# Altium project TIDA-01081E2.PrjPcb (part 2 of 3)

## Sheet TIDA-01081E2_DigitalIO.SchDoc: Isolated Power & Data Interface
size 431 x 279 mm; Date: Not shown in title block; ApprovedBy: Not shown in title block; CheckedBy: Not shown in title block; Author: Not shown in title block; CompanyName: Not shown in title block; DrawnBy: SG; Engineer: Not shown in title block; Organization: Not shown in title block; Address1: Not shown in title block; Address2: Not shown in title block; Address3: Not shown in title block; Address4: Not shown in title block; DocumentNumber: 7; Revision: Use project parameter SCH_Rev; SheetNumber: 7; SheetTotal: 8; PageSetup: Record=PageOptions¦CenterHorizontal=True¦CenterVertical=True¦PrintScale=0.94¦XCorrection=1.00¦YCorrection=1.00¦PrintKind=0¦BorderSize=5000000¦LeftOffset=0¦BottomOffset=0¦Orientation=2¦PaperLength=4200¦PaperWidth=2970¦Scale=100¦PaperSource=7¦PrintQuality=600¦MediaType=1¦DitherType=10¦PrintScaleMode=1¦PaperKind=A3¦PaperIndex=8
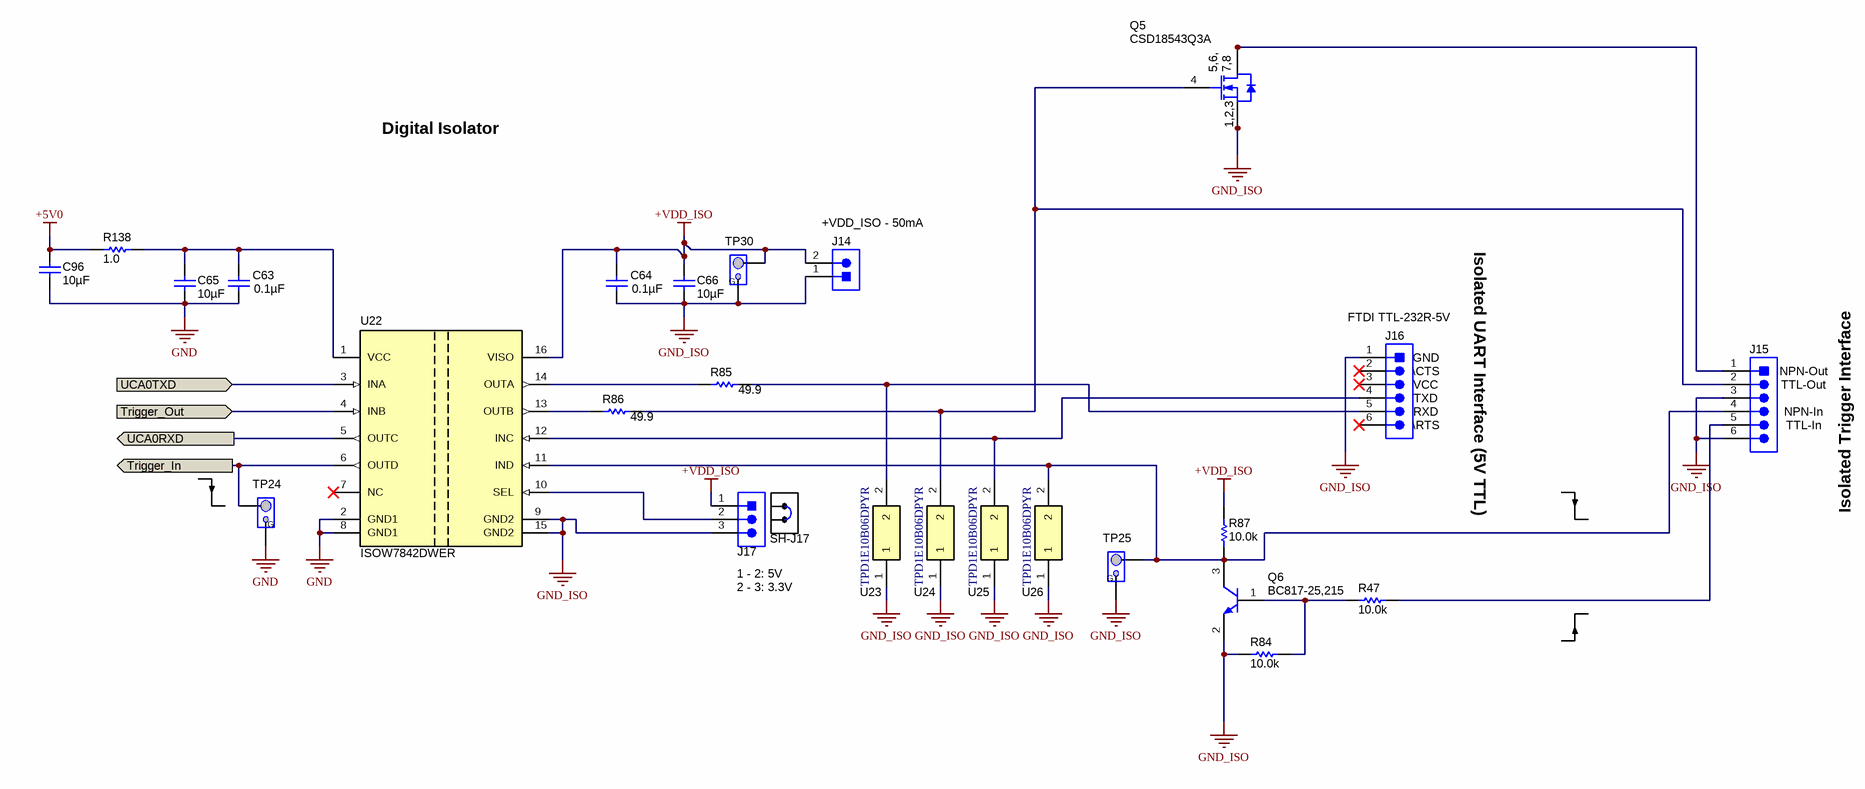
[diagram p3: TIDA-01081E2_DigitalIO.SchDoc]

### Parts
C63  ValueDisplayed: 0.1µF  [0603_HV]  (hidden comment: GCM188R71C104KA37J)
C64  ValueDisplayed: 0.1µF  [0603_HV]  (hidden comment: GCM188R71C104KA37J)
C65  ValueDisplayed: 10µF  [0603]  (hidden comment: GRM188Z71A106MA73D)
C66  ValueDisplayed: 10µF  [0603]  (hidden comment: GRM188Z71A106MA73D)
C96  ValueDisplayed: 10µF  [0805_HV]  (hidden comment: GRM21BR6YA106KE43L)
J14  61300211121  [WURTH_61300211121]  (value not drawn)
J15  61300611121  [WURTH_61300611121]  (value not drawn)
J16  61300611121  [WURTH_61300611121]  (value not drawn)
J17  61300311121  [WURTH_61300311121]  (value not drawn)
Q5  CSD18543Q3A  [DNH0008A]
Q6  BC817-25,215  [SOT-23]
R47  ValueDisplayed: 10.0k  [0603]  (hidden comment: CRCW060310K0FKEA)
R84  ValueDisplayed: 10.0k  [0603]  (hidden comment: CRCW060310K0FKEA)
R85  ValueDisplayed: 49.9  [0603]  (hidden comment: CRCW060349R9FKEA)
R86  ValueDisplayed: 49.9  [0603]  (hidden comment: CRCW060349R9FKEA)
R87  ValueDisplayed: 10.0k  [0603]  (hidden comment: CRCW060310K0FKEA)
R138  ValueDisplayed: 1.0  [0603]  (hidden comment: CRCW06031R00JNEA)
SH-J17  969102-0000-DA  [SNT-100-BK-G]  (value not drawn)
TP24  TESTPOINT_PIGTAIL  [TESTPOINT_PIGTAIL]  (value not drawn)  (no BOM)
TP25  TESTPOINT_PIGTAIL  [TESTPOINT_PIGTAIL]  (value not drawn)  (no BOM)
TP30  TESTPOINT_PIGTAIL  [TESTPOINT_PIGTAIL]  (value not drawn)  (no BOM)
U22  ISOW7842DWER  [DWE0016A]
U23  TPD1E10B06DPYR  [DPY0002A]
U24  TPD1E10B06DPYR  [DPY0002A]
U25  TPD1E10B06DPYR  [DPY0002A]
U26  TPD1E10B06DPYR  [DPY0002A]

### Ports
Trigger_In (out), Trigger_Out (in), UCA0RXD (out), UCA0TXD (in)

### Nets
+5V0: C96.1 R138.2
+VDD_ISO: C64.2 C66.1 J14.2 J17.1 R87.2 TP30.1 U22.16(VISO)
GND: C63.1 C65.2 C96.2 TP24.2 U22.2(GND1) U22.8(GND1)
GND_ISO: C64.1 C66.2 J14.1 J15.3 J15.6 J16.1 J17.3 Q5.1(S) Q5.2(S) Q5.3(S) Q6.2(E) R84.1 TP25.2 TP30.2 U22.9(GND2) U22.15(GND2) U23.1 U24.1 U25.1 U26.1
Trigger_In: TP24.1 U22.6(OUTD) ; port Trigger_In
Trigger_Out: U22.4(INB) ; port Trigger_Out
UCA0RXD: U22.5(OUTC) ; port UCA0RXD
UCA0TXD: U22.3(INA) ; port UCA0TXD
NetC63_2: C63.2 C65.1 R138.1 U22.1(VCC)
NetJ15_1: J15.1 Q5.5(D) Q5.6(D) Q5.7(D) Q5.8(D) Q5.9(D)
NetJ15_2: J15.2 Q5.4(G) R86.2 U24.2
NetJ15_4: J15.4 Q6.3(C) R87.1 TP25.1 U22.11(IND) U26.2
NetJ15_5: J15.5 R47.2
NetJ16_4: J16.4 U22.12(INC) U25.2
NetJ16_5: J16.5 R85.2 U23.2
NetJ17_2: J17.2 U22.10(SEL)
NetQ6_1: Q6.1(B) R47.1 R84.2
NetR85_1: R85.1 U22.14(OUTA)
NetR86_1: R86.1 U22.13(OUTB)

Not connected (* = marked no-connect by the designer): J16 2* 3* 6*; U22 7(NC)*

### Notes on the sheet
- Digital Isolator
- (near J14) +VDD_ISO - 50mA
- (near J16) FTDI TTL-232R-5V
- (near J16) GND
- (near J16) \CTS
- (near J16) VCC
- (near J16) TXD
- (near J16) RXD
- Isolated UART Interface (5V TTL)
- (near J15) NPN-In
- (near J15) TTL-Out
- (near J15) NPN-Out
- Isolated Trigger Interface
- (near J16) \RTS
- (near J15) TTL-In
- 1 - 2: 5V
- 2 - 3: 3.3V

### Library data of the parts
C63 C64 = GCM188R71C104KA37J: CAP, CERM, 0.1 µF, 16 V, +/- 10%, X7R, 0603_095; Manufacturer: MuRata; Polarized: N; CompType: Capacitor; Value: 0.1uF; U/M: EA; Cap_F: 0.0000001; Tolerance_%: 10; Value1: Unknown; VDC_V: 16; Value2: 16V; TaMin_C: -55; TaMax_C: 125; Cap_Case: 0603
C65 C66 = GRM188Z71A106MA73D: CAP, CERM, 10 µF, 10 V, +/- 20%, X7R, 0603; Manufacturer: MuRata; Polarized: N; CompType: Capacitor; Value: 10uF; U/M: EA; Cap_F: 0.00001; Tolerance_%: 20; Value1: Unknown; VDC_V: 10; Value2: 10V; TaMin_C: -55; TaMax_C: 125; SizeArea_mm2: 1.28; SizeAreaWB_mm2: 4.68; SizeX_mm: 1.6; SizeY_mm: 0.8; SizeZ_mm: 1; AEC Category: Q200; Green_Lifecycle: Active; Green_REACh: Passed
C96 = GRM21BR6YA106KE43L: CAP, CERM, 10 µF, 35 V,+/- 10%, X5R, 0805; Manufacturer: MuRata; Polarized: N; CompType: Capacitor; Value: 10uF; U/M: EA; Cap_F: 0.00001; Tolerance_%: 10; VDC_V: 35; Value2: 35V; TaMin_C: -55; TaMax_C: 85; Cap_Case: 0805; SizeArea_mm2: 2.5; SizeAreaWB_mm2: 6.75; SizeX_mm: 2; SizeY_mm: 1.25; SizeZ_mm: 1.45; AEC Category: Q200; Green_Lifecycle: Active; Green_REACh: Passed
J14 = 61300211121: Header, 2.54 mm, 2x1, Gold, TH; Manufacturer: Wurth Elektronik; SymbolCreator: a0412235
J15 J16 = 61300611121: Header, 2.54 mm, 6x1, Gold, TH; Manufacturer: Wurth Elektronik; SymbolCreator: a0412235
J17 = 61300311121: Header, 2.54 mm, 3x1, Gold, TH; Manufacturer: Wurth Elektronik; SymbolCreator: a0799628
Q5 = CSD18543Q3A: MOSFET, N-CH, 60 V, 35 A, DNH0008A (VSONP-8); Manufacturer: Texas Instruments; Alternate Manufacturer: None; U/M: EA; ChType: N; Value: 60V; VdsMax_V: 60; Value1: 0.012 ohm; Rdson45_ohm: 0.012; Value2: 11.1 nC; QgTyp_nC: 11.1; Vgs_V: 20; IdsMax_A: 35; SizeAreaWB_mm2: 18.49; SizeArea_mm2: 10.89; SizeX_mm: 3.3; SizeZ_mm: 0.9; AEC Category: Q101
Q6 = BC817-25,215, Nexperia: Transistor, NPN, 45 V, 0.5 A, SOT-23; CompType: BJT; PNP: 0; NPN: 1; Vceo_V: 45; Vcesat1_V: 0.7; Value: 45 V; IcRated_A: 0.5; Value1: 0.5 A; HfeMax: 400; TaMin_C: -65; TaMax_C: 150; SizeAreaWB_mm2: 14; SizeArea_mm2: 7.5; SizeX_mm: 2.5; SizeY_mm: 3; SizeZ_mm: 1.1; U/M: EA; AEC Category: Q101; AEC Qualified: N
R47 R84 R87 = CRCW060310K0FKEA: RES, 10.0 k, 1%, 0.1 W, 0603; Manufacturer: Vishay-Dale; CompType: Resistor; Value: 10.0k; Res_ohm: 10000; Value_Code: 10k0; Tolerance_%: 1; Power_W: 0.1; Value2: 0.1W; VDC_V: 75; TempCo: 100 ppm/C; SizeArea_mm2: 1.28; SizeX_mm: 1.6; SizeY_mm: 0.8; EIA_Code: E96; U/M: EA; AEC Category: Q200; Green_Lifecycle: Active; Green_REACh: Passed
R85 R86 = CRCW060349R9FKEA: RES, 49.9, 1%, 0.1 W, 0603; Manufacturer: Vishay-Dale; CompType: Resistor; Value: 49.9; Value_Code: 49R9; Tolerance_%: 1; Power_W: 0.1; Value2: 0.1W; VDC_V: 75; TempCo: 100 ppm/C; SizeArea_mm2: 1.28; SizeX_mm: 1.6; SizeY_mm: 0.8; EIA_Code: E96; U/M: EA; AEC Category: Q200
R138 = CRCW06031R00JNEA: RES, 1.0, 5%, 0.1 W, 0603; Manufacturer: Vishay-Dale; CompType: Resistor; Value: 1.0; Res_ohm: 1; Value_Code: 1R00; Tolerance_%: 5; Power_W: 0.1; Value2: 0.1W; VDC_V: 75; TempCo: 200 ppm/C; EIA_Code: E24; U/M: EA; AEC Category: Q200; SizeArea_mm2: 1.28; SizeX_mm: 1.6; SizeY_mm: 0.8; Green_Lifecycle: Active; Green_REACh: Passed
SH-J17 = 969102-0000-DA: Shunt, 100mil, Gold plated, Black; Manufacturer: 3M; Alternate Manufacturer: Samtec; Value: 1x2; Note: You can "mate" this to a header by matching the designator.  i.e. use SH-J3 for header J3
TP24 TP25 TP30 = TESTPOINT_PIGTAIL: PIGTAIL; Manufacturer: Texas Instruments; SymbolCreator: Altium
U22 = ISOW7842DWER: High-Performance, 5000-VRMS Reinforced Quad-Channel Digital Isolators With Integrated High-Efficiency, Low-Emissions DC-DC Converter, DWE0016A (SOIC-16); Manufacturer: Texas Instruments; SymbolCreator: Altium; SizeArea_mm2: 106.09; SizeAreaWB_mm2: 151.29; SizeX_mm: 10.3; SizeZ_mm: 2.65; CompType: IC; U/M: EA
U23-U26 = TPD1E10B06DPYR: ESD in 0402 Package with 10 pF Capacitance and 6 V Breakdown, 1 Channel, -40 to +125 degC, 2-pin X2SON (DPY), Green (RoHS & no Sb/Br); Manufacturer: Texas Instruments; Alternate PartNumber: Equivalent; Breakdown Voltage(Min)(V): 6; Eco-Plan: TBD; IEC 61000-4-2 Air-Gap(+/- kV): 30; IO Capacitance(Typ)(pF): 10; SubFamily: ESD Solution

## Sheet TIDA-01081E2_EVM_Hardware.SchDoc: Hardware
size 431 x 279 mm; Date: Not shown in title block; ApprovedBy: Not shown in title block; CheckedBy: Not shown in title block; Author: Not shown in title block; CompanyName: Not shown in title block; DrawnBy: JS; Engineer: Not shown in title block; Organization: Not shown in title block; Address1: Not shown in title block; Address2: Not shown in title block; Address3: Not shown in title block; Address4: Not shown in title block; DocumentNumber: 8; Revision: Use project parameter SCH_Rev; SheetNumber: 8; SheetTotal: 8; PageSetup: Record=PageOptions¦CenterHorizontal=True¦CenterVertical=True¦PrintScale=1.00¦XCorrection=1.00¦YCorrection=1.00¦PrintKind=0¦BorderSize=5000000¦LeftOffset=0¦BottomOffset=0¦Orientation=2¦PaperLength=1000¦PaperWidth=1000¦Scale=100¦PaperSource=15¦PrintQuality=600¦MediaType=1¦DitherType=10¦PaperKind=Letter¦PrintScaleMode=1
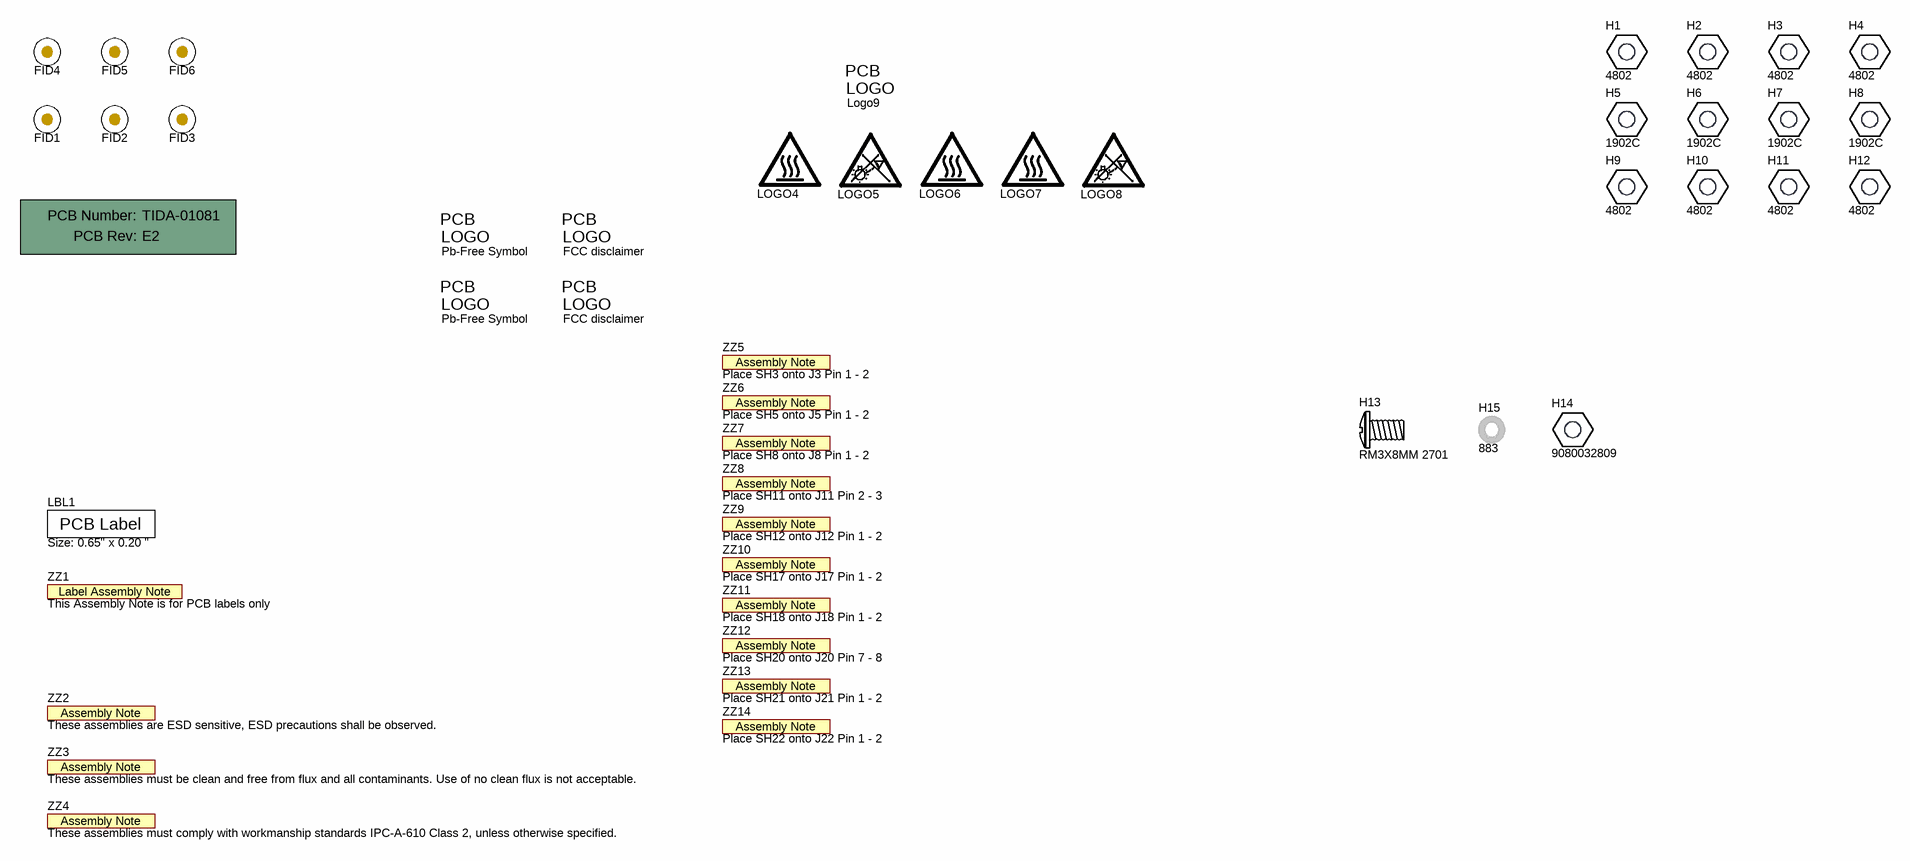
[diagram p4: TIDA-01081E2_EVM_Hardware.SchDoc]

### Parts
!PCB1  Printed Circuit Board  (value not drawn)  (mechanical)
FID1  Fiducial  [Fiducial10-20]  (value not drawn)
FID2  Fiducial  [Fiducial10-20]  (value not drawn)
FID3  Fiducial  [Fiducial10-20]  (value not drawn)
FID4  Fiducial  [Fiducial10-20]  (value not drawn)
FID5  Fiducial  [Fiducial10-20]  (value not drawn)
FID6  Fiducial  [Fiducial10-20]  (value not drawn)
H1  4802  [Keystone_4802]
H2  4802  [Keystone_4802]
H3  4802  [Keystone_4802]
H4  4802  [Keystone_4802]
H5  1902C  [Keystone_1902C]
H6  1902C  [Keystone_1902C]
H7  1902C  [Keystone_1902C]
H8  1902C  [Keystone_1902C]
H9  4802  [Keystone_4802]
H10  4802  [Keystone_4802]
H11  4802  [Keystone_4802]
H12  4802  [Keystone_4802]
H13  RM3X8MM 2701  [APM_RM3X8MM 2701]  (mechanical)
H14  9080032809  [9080032809]
H15  883  [Keystone_883]  (mechanical)
LBL1  Size: 0.65" x 0.20 "  [Label_650x200]
Logo2  Pb-Free Symbol  [Pb-Free_Overlay_Small]  (no BOM)
Logo3  FCC disclaimer  [FCC_disclaimer]  (no BOM)
LOGO4  CAUTION HOT SURFACE  [IEC_HotSurface_Small]  (value not drawn)  (no BOM)
LOGO5  LED WARNING  [LED_Warning]  (value not drawn)  (no BOM)
LOGO6  CAUTION HOT SURFACE  [IEC_HotSurface_Small]  (value not drawn)  (no BOM)
LOGO7  CAUTION HOT SURFACE  [IEC_HotSurface_Small]  (value not drawn)  (no BOM)
LOGO8  LED WARNING  [LED_Warning]  (value not drawn)  (no BOM)
Logo9  CAUTION.  READ USER GUIDE BEFORE USE  [IEC_Caution_Small]  (value not drawn)  (no BOM)
Logo11  Pb-Free Symbol  [Pb-Free_Overlay_Small]  (no BOM)
Logo12  FCC disclaimer  [FCC_disclaimer]  (no BOM)
ZZ1  This Assembly Note is for PCB labels only  [AssemblyNoteLabel]  (no BOM)
ZZ2  These assemblies are ESD sensitive, ESD precautions shall be observed.  [AssemblyNote]  (no BOM)
ZZ3  These assemblies must be clean and free from flux and all contaminants. Use of no clean flux is not acceptable.  [AssemblyNote]  (no BOM)
ZZ4  These assemblies must comply with workmanship standards IPC-A-610 Class 2, unless otherwise specified.  [AssemblyNote]  (no BOM)
ZZ5  Place SH3 onto J3 Pin 1 - 2  [AssemblyNote]  (no BOM)
ZZ6  Place SH5 onto J5 Pin 1 - 2  [AssemblyNote]  (no BOM)
ZZ7  Place SH8 onto J8 Pin 1 - 2  [AssemblyNote]  (no BOM)
ZZ8  Place SH11 onto J11 Pin 2 - 3  [AssemblyNote]  (no BOM)
ZZ9  Place SH12 onto J12 Pin 1 - 2  [AssemblyNote]  (no BOM)
ZZ10  Place SH17 onto J17 Pin 1 - 2  [AssemblyNote]  (no BOM)
ZZ11  Place SH18 onto J18 Pin 1 - 2  [AssemblyNote]  (no BOM)
ZZ12  Place SH20 onto J20 Pin 7 - 8  [AssemblyNote]  (no BOM)
ZZ13  Place SH21 onto J21 Pin 1 - 2  [AssemblyNote]  (no BOM)
ZZ14  Place SH22 onto J22 Pin 1 - 2  [AssemblyNote]  (no BOM)

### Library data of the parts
!PCB1 = PCB: Manufacturer: Any; PartNumber: TIDA-01081; SymbolCreator: a0412235
FID1-FID6 = Fiducial: Fiducial mark.  There is nothing to buy or mount.; SymbolCreator: codlsc
H1-H4 H9-H12 = 4802: Standoff, Hex, Male/Female, 4-40, Nylon, 1/2"; Manufacturer: Keystone; SymbolCreator: a0412235; Green_Lifecycle: Active; Green_REACh: Passed
H5-H8 = 1902C: Standoff, Hex, 0.5"L #4-40 Nylon; Manufacturer: Keystone; CompType: Hardware
H13 = CMP-0003717-1: MACHINE SCREW PAN PHILLIPS M3; Manufacturer: APM HEXSEAL; CompType: Standoff
H14 = CMP-0003947-1: Hex Nuts: M3 X .5MM pitch DIN 934 A2 - 304 Stainless; Manufacturer: InStock Fasteners; CompType: Standoff
H15 = CMP-0078324-1: Manufacturer: Keystone; CompType: Nylon Spacer
LBL1 = THT-14-423-10: Thermal Transfer Printable Labels, 0.650" W x 0.200" H - 10,000 per roll; Manufacturer: Brady; SymbolCreator: a0412235; CompType: Label
Logo2 Logo11 = Pb-Free: SymbolCreator: a0412235
Logo3 Logo12 = FCC_disclaimer: SymbolCreator: codlsc
LOGO4 LOGO6 LOGO7 = IEC_HotSurface: IEC 61010-1 Hot Surface Warning; SymbolCreator: a0412235
LOGO5 LOGO8 = LED_Warning: LED Warning Symbol; SymbolCreator: a0412235
Logo9 = IEC_Caution: IEC 61010-1 Caution Warning; SymbolCreator: a0412235
ZZ1 = AssemblyNoteLabel: SymbolCreator: a0412235
ZZ2-ZZ14 = AssemblyNote: SymbolCreator: codlsc

## Sheet TIDA-01081E2_LED_Board.SchDoc: LED Board
size 431 x 279 mm; Date: Not shown in title block; ApprovedBy: Not shown in title block; CheckedBy: Not shown in title block; Author: Not shown in title block; CompanyName: Not shown in title block; DrawnBy: SG; Engineer: Not shown in title block; Organization: Not shown in title block; Address1: Not shown in title block; Address2: Not shown in title block; Address3: Not shown in title block; Address4: Not shown in title block; DocumentNumber: 5; Revision: Use project parameter SCH_Rev; SheetNumber: 5; SheetTotal: 8; PageSetup: Record=PageOptions¦CenterHorizontal=True¦CenterVertical=True¦PrintScale=0.94¦XCorrection=1.00¦YCorrection=1.00¦PrintKind=0¦BorderSize=5000000¦LeftOffset=0¦BottomOffset=0¦Orientation=2¦PaperLength=4200¦PaperWidth=2970¦Scale=100¦PaperSource=7¦PrintQuality=600¦MediaType=1¦DitherType=10¦PrintScaleMode=1¦PaperKind=A3¦PaperIndex=8
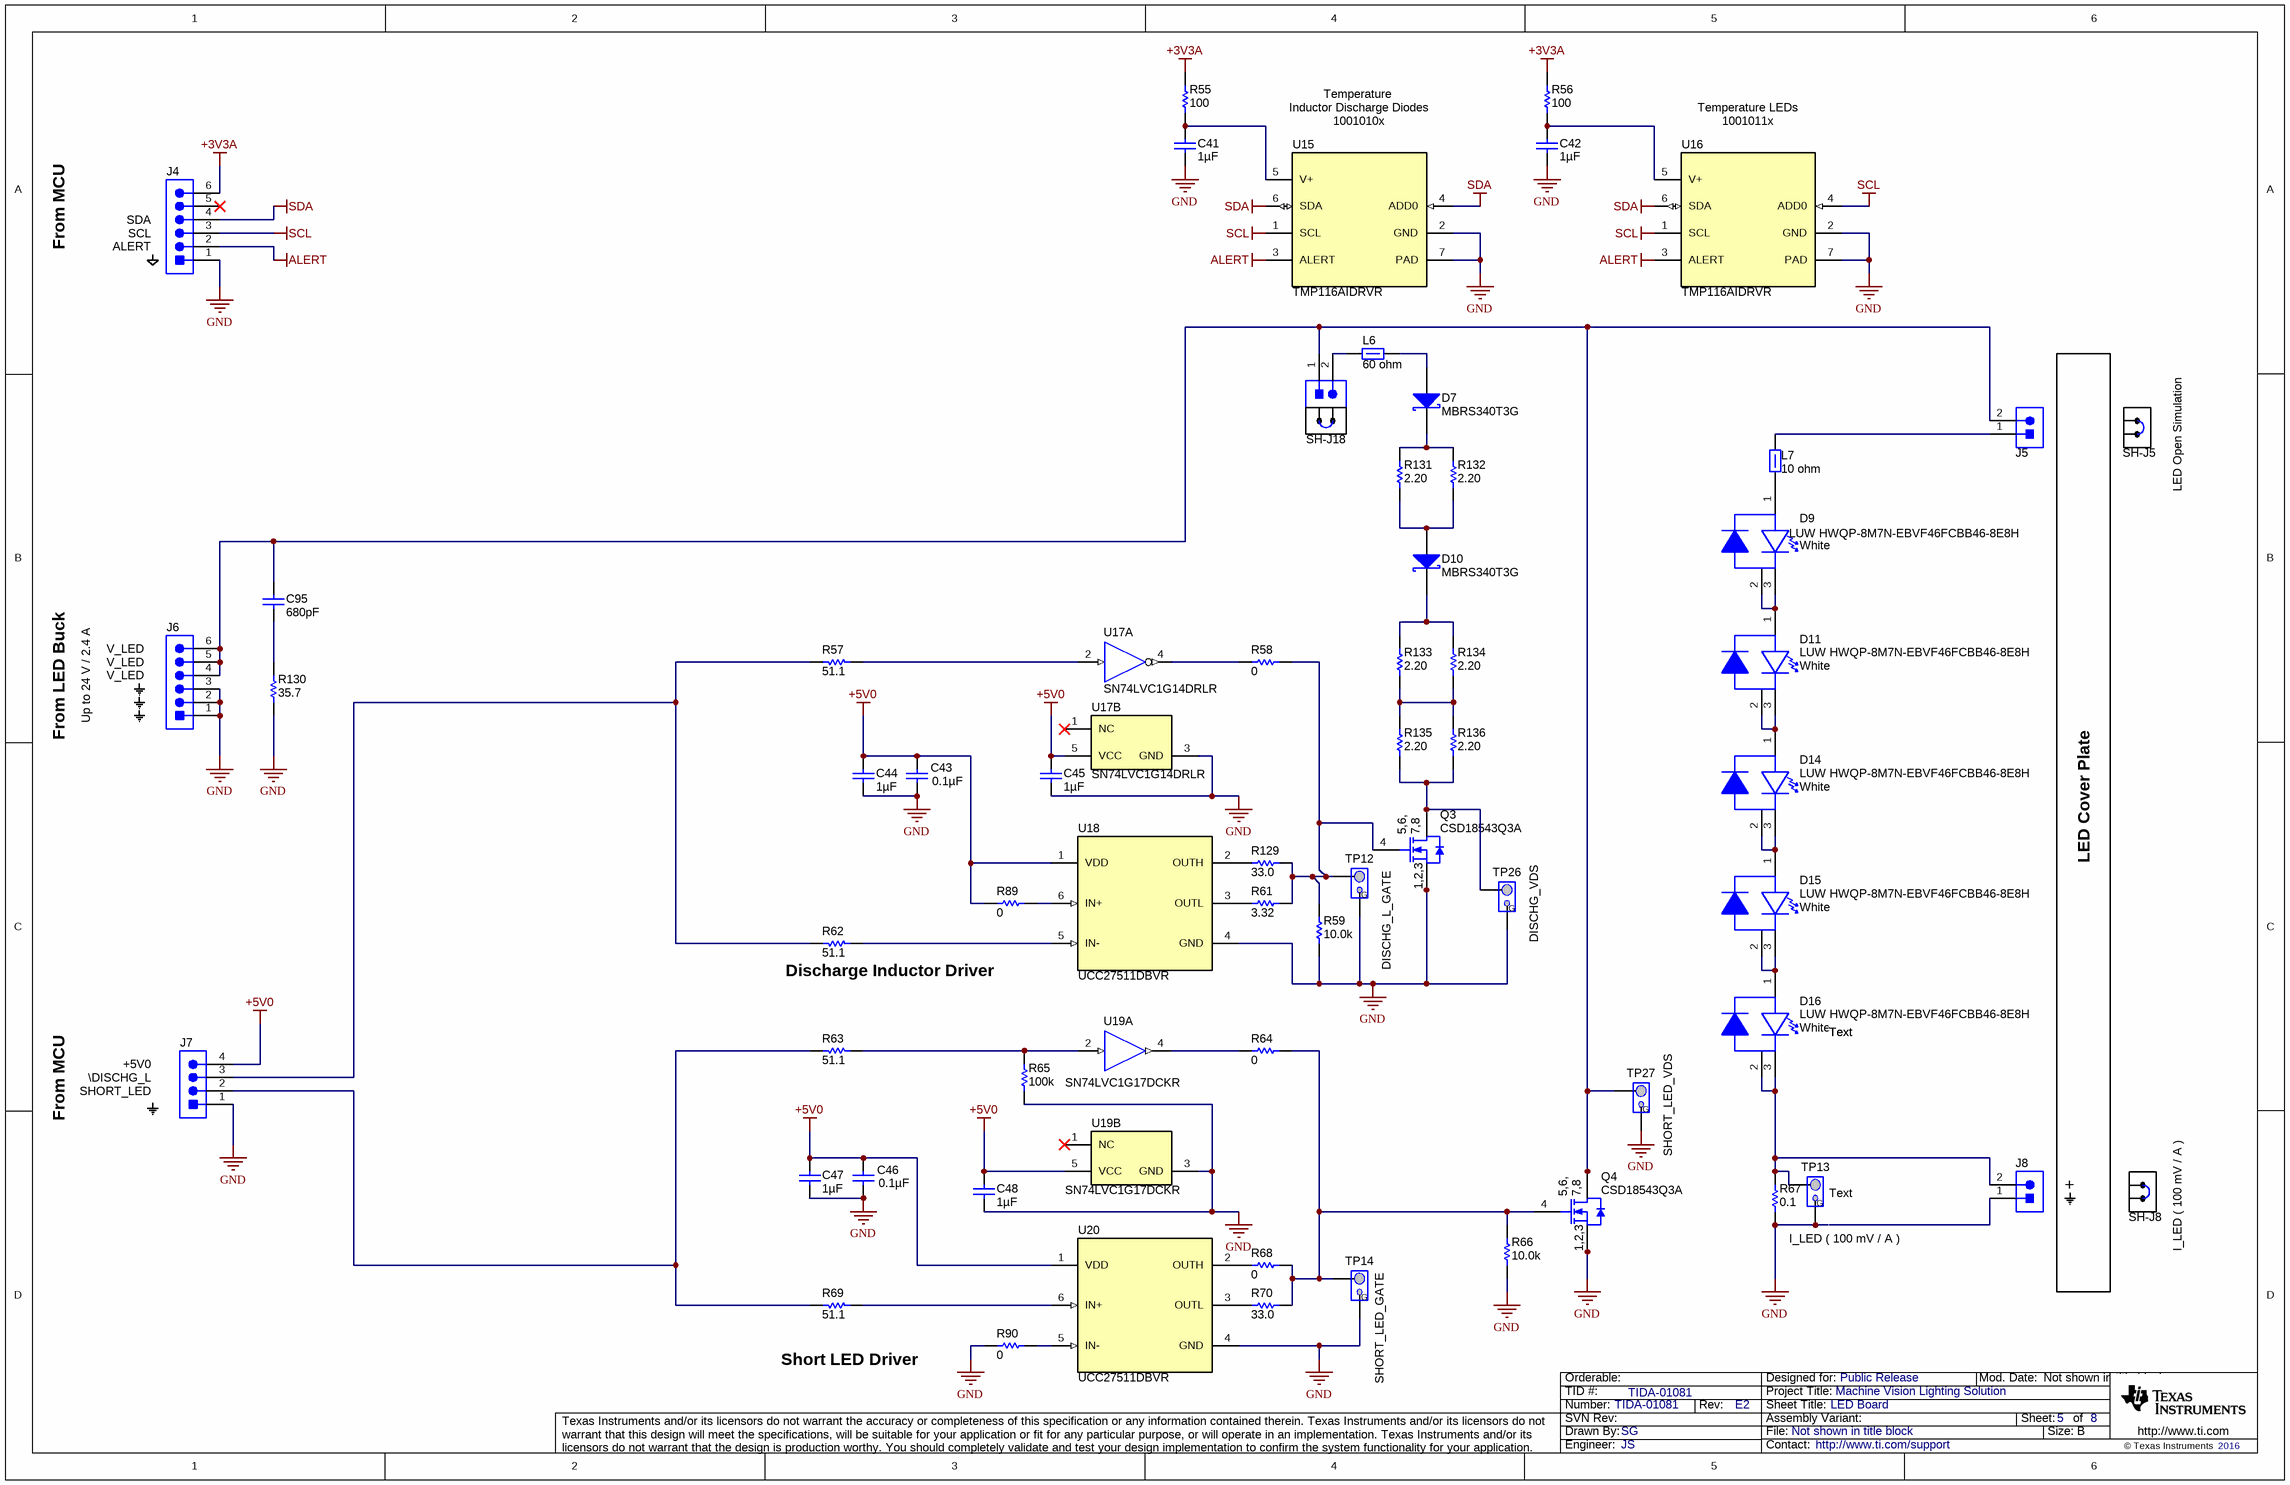
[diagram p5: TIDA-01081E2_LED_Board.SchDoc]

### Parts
C41  ValueDisplayed: 1µF  [0603]  (hidden comment: GRM188R71C105KE15D)
C42  ValueDisplayed: 1µF  [0603]  (hidden comment: GRM188R71C105KE15D)
C43  ValueDisplayed: 0.1µF  [0603_HV]  (hidden comment: GCM188R71C104KA37J)
C44  ValueDisplayed: 1µF  [0603]  (hidden comment: GRM188R71C105KE15D)
C45  ValueDisplayed: 1µF  [0603]  (hidden comment: GRM188R71C105KE15D)
C46  ValueDisplayed: 0.1µF  [0603_HV]  (hidden comment: GCM188R71C104KA37J)
C47  ValueDisplayed: 1µF  [0603]  (hidden comment: GRM188R71C105KE15D)
C48  ValueDisplayed: 1µF  [0603]  (hidden comment: GRM188R71C105KE15D)
C95  ValueDisplayed: 680pF  [1206]  (hidden comment: 12061A681JAT2A)
D7  MBRS340T3G  [SMC]
D9  LUW HWQP-8M7N-EBVF46FCBB46-8E8H  value White  [LUW_HWQP_White-IHT]
D10  MBRS340T3G  [SMC]
D11  LUW HWQP-8M7N-EBVF46FCBB46-8E8H  value White  [LUW_HWQP_White-IHT]
D14  LUW HWQP-8M7N-EBVF46FCBB46-8E8H  value White  [LUW_HWQP_White-IHT]
D15  LUW HWQP-8M7N-EBVF46FCBB46-8E8H  value White  [LUW_HWQP_White-IHT]
D16  LUW HWQP-8M7N-EBVF46FCBB46-8E8H  value White  [LUW_HWQP_White-IHT]
J4  61300611121  [WURTH_61300611121]  (value not drawn)
J5  TSW-102-17-G-S  [Samtec_TSW-102-17-x-S]  (value not drawn)
J6  61300611121  [WURTH_61300611121]  (value not drawn)
J7  61300411121  [WURTH_61300411121]  (value not drawn)
J8  61300211121  [WURTH_61300211121]  (value not drawn)
J18  TSW-102-17-G-S  [Samtec_TSW-102-17-x-S]  (value not drawn)
L6  ValueDisplayed: 60 ohm  [1806_HighSpeed]  (hidden comment: 742792410)
L7  ValueDisplayed: 10 ohm  [0805_HV]  (hidden comment: 742792011)
Q3  CSD18543Q3A  [DNH0008A]
Q4  CSD18543Q3A  [DNH0008A]
R55  ValueDisplayed: 100  [0603]  (hidden comment: RC0603FR-07100RL)
R56  ValueDisplayed: 100  [0603]  (hidden comment: RC0603FR-07100RL)
R57  ValueDisplayed: 51.1  [0603]  (hidden comment: RC0603FR-0751R1L)
R58  ValueDisplayed: 0  [0603]  (hidden comment: RC0603JR-070RL)
R59  ValueDisplayed: 10.0k  [0603]  (hidden comment: RC0603FR-0710KL)
R61  ValueDisplayed: 3.32  [0603]  (hidden comment: RC0603FR-073R32L)
R62  ValueDisplayed: 51.1  [0603]  (hidden comment: RC0603FR-0751R1L)
R63  ValueDisplayed: 51.1  [0603]  (hidden comment: RC0603FR-0751R1L)
R64  ValueDisplayed: 0  [0603]  (hidden comment: RC0603JR-070RL)
R65  ValueDisplayed: 100k  [0603]  (hidden comment: RC0603FR-07100KL)
R66  ValueDisplayed: 10.0k  [0603]  (hidden comment: RC0603FR-0710KL)
R67  ValueDisplayed: 0.1  [1206]  (hidden comment: ERJ-8BWFR100V)
R68  ValueDisplayed: 0  [0603]  (hidden comment: RC0603JR-070RL)
R69  ValueDisplayed: 51.1  [0603]  (hidden comment: RC0603FR-0751R1L)
R70  ValueDisplayed: 33.0  [0603]  (hidden comment: RC0603FR-0733RL)
R89  ValueDisplayed: 0  [0603]  (hidden comment: RC0603JR-070RL)
R90  ValueDisplayed: 0  [0603]  (hidden comment: RC0603JR-070RL)
R129  ValueDisplayed: 33.0  [0603]  (hidden comment: RC0603FR-0733RL)
R130  ValueDisplayed: 35.7  [1206]  (hidden comment: RC1206FR-0735R7L)
R131  ValueDisplayed: 2.20  [MMB0207]  (hidden comment: MMB02070C2208FB200)
R132  ValueDisplayed: 2.20  [MMB0207]  (hidden comment: MMB02070C2208FB200)
R133  ValueDisplayed: 2.20  [MMB0207]  (hidden comment: MMB02070C2208FB200)
R134  ValueDisplayed: 2.20  [MMB0207]  (hidden comment: MMB02070C2208FB200)
R135  ValueDisplayed: 2.20  [MMB0207]  (hidden comment: MMB02070C2208FB200)
R136  ValueDisplayed: 2.20  [MMB0207]  (hidden comment: MMB02070C2208FB200)
SH-J5  969102-0000-DA  [SNT-100-BK-G]  (value not drawn)
SH-J8  969102-0000-DA  [SNT-100-BK-G]  (value not drawn)
SH-J18  969102-0000-DA  [SNT-100-BK-G]  (value not drawn)
TP12  TESTPOINT_PIGTAIL  [TESTPOINT_PIGTAIL]  (value not drawn)  (no BOM)
TP13  TESTPOINT_PIGTAIL  [TESTPOINT_PIGTAIL]  (value not drawn)  (no BOM)
TP14  TESTPOINT_PIGTAIL  [TESTPOINT_PIGTAIL]  (value not drawn)  (no BOM)
TP26  TESTPOINT_PIGTAIL  [TESTPOINT_PIGTAIL]  (value not drawn)  (no BOM)
TP27  TESTPOINT_PIGTAIL  [TESTPOINT_PIGTAIL]  (value not drawn)  (no BOM)
U15  TMP116AIDRVR  [DRV0006A]
U16  TMP116AIDRVR  [DRV0006A]
U17  SN74LVC1G14DRLR  [DRL0005A]  (parts A,B of 2)
U18  UCC27511DBVR  [DBV0006A_N]
U19  SN74LVC1G17DCKR  [DCK0005A_N]  (parts A,B of 2)
U20  UCC27511DBVR  [DBV0006A_N]

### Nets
+3V3A: J4.6 R55.1 R56.1
+5V0: C43.2 C44.2 C45.2 C46.2 C47.2 C48.2 J7.4 R89.1 U17.5(VCC) U18.1(VDD) U19.5(VCC) U20.1(VDD)
ALERT: J4.2 U15.3(ALERT) U16.3(ALERT)
GND: C41.2 C42.2 C43.1 C44.1 C45.1 C46.1 C47.1 C48.1 J4.1 J6.1 J6.2 J6.3 J7.1 J8.1 Q3.1(S) Q3.2(S) Q3.3(S) Q4.1(S) Q4.2(S) Q4.3(S) R59.1 R65.1 R66.1 R67.2 R90.1 R130.1 TP12.2 TP13.2 TP14.2 TP26.2 TP27.2 U15.2(GND) U15.7(PAD) U16.2(GND) U16.7(PAD) U17.3(GND) U18.4(GND) U19.3(GND) U20.4(GND)
SCL: J4.3 U15.1(SCL) U16.1(SCL) U16.4(ADD0)
SDA: J4.4 U15.4(ADD0) U15.6(SDA) U16.6(SDA)
NetC41_1: C41.1 R55.2 U15.5(V+)
NetC42_1: C42.1 R56.2 U16.5(V+)
NetC95_1: C95.1 J5.2 J6.4 J6.5 J6.6 J18.1 Q4.5(D) Q4.6(D) Q4.7(D) Q4.8(D) Q4.9(D) TP27.1
NetC95_2: C95.2 R130.2
NetD7_1: D7.1(K) R131.2 R132.2
NetD7_2: D7.2(A) L6.2
NetD9_1: D9.1(A) L7.1
NetD9_2: D9.2(K) D9.3(K) D11.1(A)
NetD10_1: D10.1(K) R133.2 R134.2
NetD10_2: D10.2(A) R131.1 R132.1
NetD11_2: D11.2(K) D11.3(K) D14.1(A)
NetD14_2: D14.2(K) D14.3(K) D15.1(A)
NetD15_2: D15.2(K) D15.3(K) D16.1(A)
NetD16_2: D16.2(K) D16.3(K) J8.2 R67.1 TP13.1
NetJ5_1: J5.1 L7.2
NetJ7_2: J7.2 R63.1 R69.1
NetJ7_3: J7.3 R57.1 R62.1
NetJ18_2: J18.2 L6.1
NetQ3_4: Q3.4(G) R58.2 R59.2 R61.2 R129.2 TP12.1
NetQ3_5: Q3.5(D) Q3.6(D) Q3.7(D) Q3.8(D) Q3.9(D) R135.1 R136.1 TP26.1
NetQ4_4: Q4.4(G) R64.2 R66.2 R68.2 R70.2 TP14.1
NetR57_2: R57.2 U17.2(A)
NetR58_1: R58.1 U17.4(Y)
NetR61_1: R61.1 U18.3(OUTL)
NetR62_2: R62.2 U18.5(IN-)
NetR63_2: R63.2 R65.2 U19.2(A)
NetR64_1: R64.1 U19.4(Y)
NetR68_1: R68.1 U20.2(OUTH)
NetR69_2: R69.2 U20.6(IN+)
NetR70_1: R70.1 U20.3(OUTL)
NetR89_2: R89.2 U18.6(IN+)
NetR90_2: R90.2 U20.5(IN-)
NetR129_1: R129.1 U18.2(OUTH)
NetR133_1: R133.1 R134.1 R135.2 R136.2

Not connected (* = marked no-connect by the designer): J4 5*; U17 1(NC)*; U19 1(NC)*

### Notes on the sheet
- Temperature
  Inductor Discharge Diodes
  1001010x
- Temperature LEDs
  1001011x
- From MCU
- (near J4) SDA
- (near J4) SCL
- (near J4) ALERT
- (near SH-J5) LED Open Simulation
- From LED Buck
- Up to 24 V / 2.4 A
- (near J6) V_LED
- LED Cover Plate
- (near TP26) DISCHG_VDS
- (near R62) Discharge Inductor Driver
- DISCHG_L_GATE
- +5V0
- SHORT_LED
- \DISCHG_L
- (near TP27) SHORT_LED_VDS
- Text
- I_LED ( 100 mV / A )
- +
- (near TP13) Text
- (near SH-J8) I_LED ( 100 mV / A )
- (near R69) Short LED Driver
- (near TP14) SHORT_LED_GATE

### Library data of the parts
C41 C42 C44 C45 C47 C48 = GRM188R71C105KE15D: CAP, CERM, 1 µF, 16 V, +/- 10%, X7R, 0603; Manufacturer: MuRata; Polarized: N; CompType: Capacitor; Value: 1uF; U/M: EA; Cap_F: 0.000001; Tolerance_%: 10; Value1: Unknown; VDC_V: 16; Value2: 16V; TaMin_C: -55; TaMax_C: 125; SizeArea_mm2: 1.28; SizeAreaWB_mm2: 4.68; SizeX_mm: 1.6; SizeY_mm: 0.8; SizeZ_mm: 1; AEC Category: Q200
C43 C46 = GCM188R71C104KA37J: as C63 on sheet TIDA-01081E2_DigitalIO
C95 = 12061A681JAT2A: CAP, CERM, 680 pF, 100 V,+/- 5%, C0G/NP0, 1206; Manufacturer: AVX; Polarized: N; CompType: Capacitor; Value: 680pF; U/M: EA; Cap_F: 0.00000000068; Tolerance_%: 5; ESR_ohm: 0.281; Value1: 0.281 ohm; VDC_V: 100; Value2: 100V; TaMin_C: -55; TaMax_C: 125; SizeArea_mm2: 5.12; SizeAreaWB_mm2: 10.92; SizeX_mm: 3.2; SizeY_mm: 1.6; SizeZ_mm: 1.35; AEC Category: Q200; Green_Lifecycle: Not Set; Green_REACh: Incomplete
D7 D10 = MBRS340T3G: Diode, Schottky, 40 V, 3 A, SMC; Manufacturer: ON Semiconductor; U/M: EA; Vf_V: 0.525; Value: 40V; Value1: 3A; Value2: 0.525V; Io_A: 3; Vr_V: 40; TJmax_C: 125; RJC_CperW: 11; SizeAreaWB_mm2: 83.2686; SizeArea_mm2: 50.5686; SizeX_mm: 8.13; SizeY_mm: 6.22; SizeZ_mm: 2.6; AEC Category: Q101; Green_Lifecycle: Active; Green_REACh: Passed
D9 D11 D14-D16 = LUW HWQP-8M7N-EBVF46FCBB46-8E8H: LED, White, SMD; Manufacturer: OSRAM; SymbolCreator: Altium; Vf_V: 3.05; Value2: 3.05V; Io_A: 1; Tjmax_C: 175; Value1: W; Angle: 120; SizeAreaWB_mm2: 22.5625; SizeArea_mm2: 14.0625; SizeX_mm: 3.75; SizeZ_mm: 0.6; U/M: EA
J4 J6 = 61300611121: as J15 on sheet TIDA-01081E2_DigitalIO
J5 J18 = CMP-0077742-1: Header, 2.54mm, 2x1, Gold, TH; Manufacturer: Samtec; Pitch_mm: 2.54; Gender: Male; Shrouded: N; Row_Count: 1; Cert_CSA: Y
J7 = 61300411121: Header, 2.54 mm, 4x1, Gold, TH; Manufacturer: Wurth Elektronik; SymbolCreator: a0412235
J8 = 61300211121: as J14 on sheet TIDA-01081E2_DigitalIO
L6 = 742792410: Ferrite Bead, 60 ohm @ 100 MHz, 6 A, 1806; Manufacturer: Wurth Elektronik; Value: 60 ohm; Imax_A: 6; DCR_ohm: 0.01; Value1: 0.01 ohm; Value2: 6A; SizeAreaWB_mm2: 14.3; SizeArea_mm2: 7.2; SizeX_mm: 4.5; SizeY_mm: 1.6; SizeZ_mm: 1.85; ZTyp@100MHz_Ohm: 60; Ztyp@1GHz_Ohm: 122.402; Green_Lifecycle: Active; Green_REACh: Passed
L7 = 742792011: Ferrite Bead, 10 ohm @ 100 MHz, 3 A, 0805; Manufacturer: Wurth Elektronik; Value: 10 ohm; Imax_A: 3; DCR_ohm: 0.025; Value1: 0.025 ohm; Value2: 3A; SizeAreaWB_mm2: 6.75; SizeArea_mm2: 2.5; SizeX_mm: 2; SizeY_mm: 1.25; SizeZ_mm: 1.45; ZTyp@100MHz_Ohm: 10; Ztyp@1GHz_Ohm: 19.272; Green_Lifecycle: Active; Green_REACh: Passed
Q3 Q4 = CSD18543Q3A: as Q5 on sheet TIDA-01081E2_DigitalIO
R55 R56 = RC0603FR-07100RL: RES, 100, 1%, 0.1 W, 0603; Manufacturer: Yageo America; CompType: Resistor; Value: 100; Value_Code: 100R; Tolerance_%: 1; Power_W: 0.1; Value2: 0.1W; VDC_V: 150; TempCo: 200 ppm/C; SizeArea_mm2: 1.28; SizeX_mm: 1.6; SizeY_mm: 0.8; EIA_Code: E96; U/M: EA; AEC Category: Q200
R57 R62 R63 R69 = RC0603FR-0751R1L: RES, 51.1, 1%, 0.1 W, 0603; Manufacturer: Yageo America; CompType: Resistor; Value: 51.1; Value_Code: 51R1; Tolerance_%: 1; Power_W: 0.1; Value2: 0.1W; VDC_V: 150; TempCo: 200 ppm/C; SizeArea_mm2: 1.28; SizeX_mm: 1.6; SizeY_mm: 0.8; EIA_Code: E96; U/M: EA; AEC Category: Q200; Green_Lifecycle: Active; Green_REACh: Passed
R58 R64 R68 R89 R90 = RC0603JR-070RL: RES, 0, 5%, 0.1 W, 0603; Manufacturer: Yageo America; CompType: Resistor; Value: 0; Value_Code: 0000; Tolerance_%: 5; Power_W: 0.1; Value2: 0.1W; VDC_V: 50; TempCo: 200 ppm/C; SizeArea_mm2: 1.28; SizeX_mm: 1.6; SizeY_mm: 0.8; SizeZ_mm: 1; EIA_Code: E24; U/M: EA; AEC Category: Q200; Green_Lifecycle: Active; Green_REACh: Passed
R59 R66 = RC0603FR-0710KL: RES, 10.0 k, 1%, 0.1 W, 0603; Manufacturer: Yageo America; CompType: Resistor; Value: 10.0k; Res_ohm: 10000; Value_Code: 10k0; Tolerance_%: 1; Power_W: 0.1; Value2: 0.1W; VDC_V: 150; TempCo: 200 ppm/C; SizeArea_mm2: 1.28; SizeX_mm: 1.6; SizeY_mm: 0.8; EIA_Code: E96; U/M: EA; AEC Category: Q200
R61 = RC0603FR-073R32L: RES, 3.32, 1%, 0.1 W, 0603; Manufacturer: Yageo America; CompType: Resistor; Value: 3.32; Value_Code: 3R32; Tolerance_%: 1; Power_W: 0.1; Value2: 0.1W; VDC_V: 150; TempCo: 200 ppm/C; SizeArea_mm2: 1.28; SizeX_mm: 1.6; SizeY_mm: 0.8; EIA_Code: E96; U/M: EA; AEC Category: Q200
R65 = RC0603FR-07100KL: RES, 100 k, 1%, 0.1 W, 0603; Manufacturer: Yageo America; CompType: Resistor; Value: 100k; Res_ohm: 100000; Tolerance_%: 1; Power_W: 0.1; Value2: 0.1W; VDC_V: 150; TempCo: 200 ppm/C; SizeArea_mm2: 1.28; SizeX_mm: 1.6; SizeY_mm: 0.8; EIA_Code: E96; U/M: EA; AEC Category: Q200
R67 = ERJ-8BWFR100V: RES, 0.1, 1%, 0.5 W, 1206; Manufacturer: Panasonic; CompType: Resistor; Value: 0.1; Value_Code: R100; Tolerance_%: 1; Power_W: 0.5; Value2: 0.5W; VDC_V: 0; TempCo: 150 ppm/C; SizeArea_mm2: 5.12; SizeX_mm: 3.2; SizeY_mm: 1.6; SizeZ_mm: 1.35; EIA_Code: E96; U/M: EA; AEC Category: Q200
R70 R129 = RC0603FR-0733RL: RES, 33.0, 1%, 0.1 W, 0603; Manufacturer: Yageo America; CompType: Resistor; Value: 33.0; Res_ohm: 33; Value_Code: 33R0; Tolerance_%: 1; Power_W: 0.1; Value2: 0.1W; VDC_V: 150; TempCo: 200 ppm/C; SizeArea_mm2: 1.28; SizeX_mm: 1.6; SizeY_mm: 0.8; U/M: EA; AEC Category: Q200; Green_Lifecycle: Active; Green_REACh: Passed
R130 = RC1206FR-0735R7L: RES, 35.7, 1%, 0.25 W, 1206; Manufacturer: Yageo America; CompType: Resistor; Value: 35.7; Value_Code: 35R7; Tolerance_%: 1; Power_W: 0.25; Value2: 0.25W; VDC_V: 200; TempCo: 100 ppm/C; SizeArea_mm2: 5.12; SizeX_mm: 3.2; SizeY_mm: 1.6; SizeZ_mm: 1.35; EIA_Code: E96; U/M: EA; AEC Category: Q200
R131-R136 = CMP-0077662-1: RES, 2.20, 1%, 1 W, AEC-Q200 Grade 0, 2.2x5.8mm; Manufacturer: Vishay/Beyschlag; Power_W: 1W; TempCo: 50 ppm/C; Value_Code: 2R20; U/M: EA; Value: 2.20; Res_ohm: 2.2; AEC Qualified: Y; VDC_V: 350V; AEC Grade: 0; AEC Category: Q200
SH-J5 = 969102-0000-DA: Shunt, 100mil, Gold plated, Black; Manufacturer: 3M; Alternate Manufacturer: Samtec; Value: 1x2; Note: You can "mate" this to a header by matching the designator.  i.e. use SH-J3 for header J3; Green_Lifecycle: Active; Green_REACh: Passed
SH-J8 SH-J18 = 969102-0000-DA: as SH-J17 on sheet TIDA-01081E2_DigitalIO
TP12-TP14 TP26 TP27 = TESTPOINT_PIGTAIL: as TP24 on sheet TIDA-01081E2_DigitalIO
U15 U16 = TMP116AIDRVR: High-Accuracy, Low-Power, Digital Temperature Sensor with SMBus and Two-Wire Serial Interface, DRV0006A (WSON-6); Alternate PartNumber: TMP116AIDRVT; Manufacturer: Texas Instruments; SymbolCreator: Altium; SizeArea_mm2: 4; SizeAreaWB_mm2: 9; SizeX_mm: 2; SizeZ_mm: 0.8; CompType: IC; U/M: EA
U17 = SN74LVC1G14DRLR: Single Schmitt-Trigger Inverter, DRL0005A, LARGE T&R; Manufacturer: Texas Instruments; Alternate PartNumber: Equivalent; VCC(Min)(V): 1.65; VCC(Max)(V): 5.5; Output Type: CMOS; ICC @ Nom Voltage(Max)(mA): 0.01; Input Type: CMOS/TTL; Bits(#): 1; F @ Nom Voltage(Max)(Mhz): 150; Rating: Catalog; Technology Family: LVC; Voltage(Nom)(V): 1.8,2.5,3.3,5; Schmitt Trigger: Yes; Output Drive (IOL/IOH)(Max)(mA): 32/-32; tpd @ Nom Voltage(Max)(ns): 11,6.5,5.5,5; Logic: Inverting; Sub-Family: Inverting Buffer/Driver; 3-State Output: No
U18 U20 = UCC27511DBVR: 4A/8A Single Channel High-speed Low-side Gate Driver, DBV0006A (SOT-23-6); Alternate PartNumber: UCC27511DBVT; Manufacturer: Texas Instruments; SymbolCreator: a0411947; SizeArea_mm2: 8.12; SizeAreaWB_mm2: 14.82; SizeX_mm: 2.8; SizeY_mm: 2.9; SizeZ_mm: 1.45; CompType: IC; U/M: EA
U19 = SN74LVC1G17DCKR: Single Schmitt-Trigger Buffer, DCK0005A, LARGE T&R; Manufacturer: Texas Instruments; Alternate PartNumber: Equivalent; VCC(Min)(V): 1.65; VCC(Max)(V): 5.5; Output Type: CMOS; ICC @ Nom Voltage(Max)(mA): 0.01; Input Type: CMOS/TTL; Bits(#): 1; F @ Nom Voltage(Max)(Mhz): 150; Rating: Catalog; Technology Family: LVC; Voltage(Nom)(V): 1.8,2.5,3.3,5; Schmitt Trigger: Yes; Output Drive (IOL/IOH)(Max)(mA): 32/-32; tpd @ Nom Voltage(Max)(ns): 11,6.5,5.5,5; Logic: True; Sub-Family: Non-Inverting Buffer/Driver; 3-State Output: No

## Sheet TIDA-01081E2_LED_Buck.SchDoc: LED Buck
size 431 x 279 mm; Date: Not shown in title block; ApprovedBy: Not shown in title block; CheckedBy: Not shown in title block; Author: Not shown in title block; CompanyName: Not shown in title block; DrawnBy: JS; Engineer: Not shown in title block; Organization: Not shown in title block; Address1: Not shown in title block; Address2: Not shown in title block; Address3: Not shown in title block; Address4: Not shown in title block; DocumentNumber: 4; Revision: Use project parameter SCH_Rev; SheetNumber: 4; SheetTotal: 8; PageSetup: Record=PageOptions¦CenterHorizontal=True¦CenterVertical=True¦PrintScale=0.94¦XCorrection=1.00¦YCorrection=1.00¦PrintKind=0¦BorderSize=5000000¦LeftOffset=0¦BottomOffset=0¦Orientation=2¦PaperLength=4200¦PaperWidth=2970¦Scale=100¦PaperSource=7¦PrintQuality=600¦MediaType=1¦DitherType=10¦PrintScaleMode=1¦PaperKind=A3¦PaperIndex=8
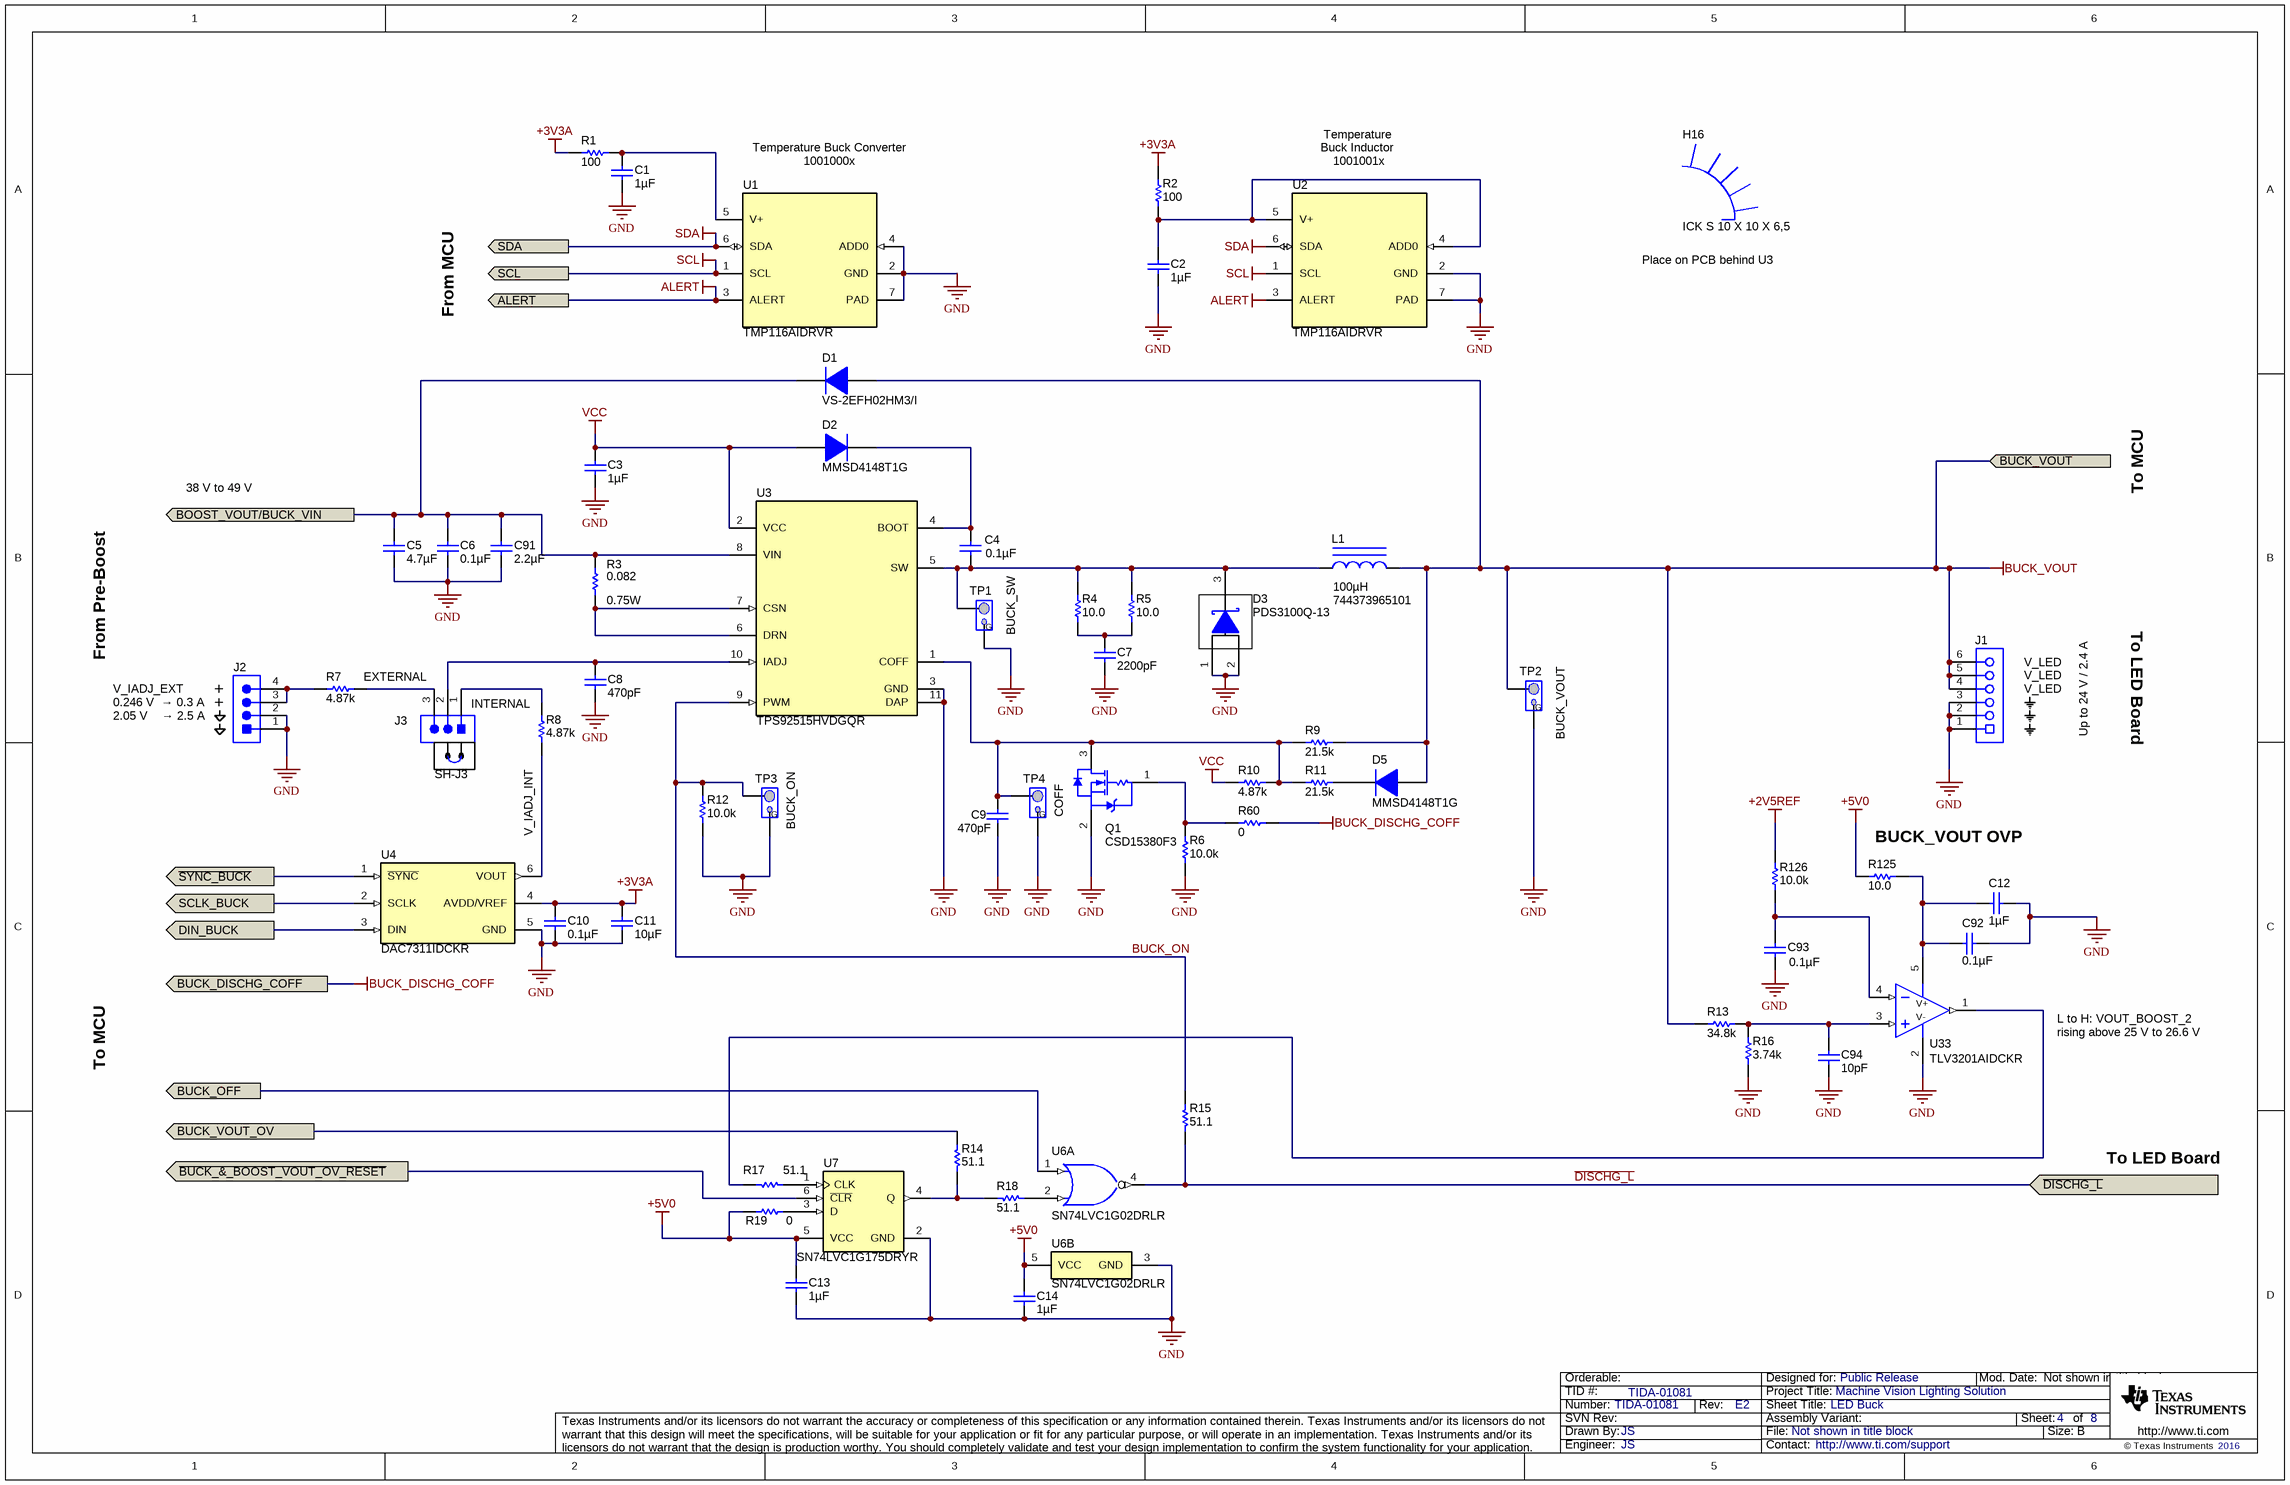
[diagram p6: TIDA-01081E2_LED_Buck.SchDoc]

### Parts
C1  ValueDisplayed: 1µF  [0603]  (hidden comment: GRM188R71C105KE15D)
C2  ValueDisplayed: 1µF  [0603]  (hidden comment: GRM188R71C105KE15D)
C3  ValueDisplayed: 1µF  [0603]  (hidden comment: GRM188R71C105KE15D)
C4  ValueDisplayed: 0.1µF  [0603_HV]  (hidden comment: GCM188R71C104KA37J)
C5  ValueDisplayed: 4.7µF  [1210_270]  (hidden comment: GRM32ER71K475KE14L)
C6  ValueDisplayed: 0.1µF  [0603_HV]  (hidden comment: GRM188R72A104KA35D)
C7  ValueDisplayed: 2200pF  [0603]  (hidden comment: CGA3E2X7R2A222K080AA)
C8  ValueDisplayed: 470pF  [0603]  (hidden comment: GCM1885C1H471JA16D)
C9  ValueDisplayed: 470pF  [0603_HV]  (hidden comment: GCM1885C1H471JA16D)
C10  ValueDisplayed: 0.1µF  [0603]  (hidden comment: C0603C104K8RACTU)
C11  ValueDisplayed: 10µF  [0603]  (hidden comment: GRM188Z71A106MA73D)
C12  ValueDisplayed: 1µF  [0603]  (hidden comment: GRM188R71C105KE15D)
C13  ValueDisplayed: 1µF  [0603]  (hidden comment: GRM188R71C105KE15D)
C14  ValueDisplayed: 1µF  [0603]  (hidden comment: GRM188R71C105KE15D)
C91  ValueDisplayed: 2.2µF  [1210_250]  (hidden comment: CGA6N3X7R2A225K230AB)
C92  ValueDisplayed: 0.1µF  [0603_HV]  (hidden comment: GCM188R71C104KA37J)
C93  ValueDisplayed: 0.1µF  [0603_HV]  (hidden comment: GCM188R71C104KA37J)
C94  ValueDisplayed: 10pF  [0603]  (hidden comment: 06035A100JAT2A)
D1  VS-2EFH02HM3/I  [DO-219AB]
D2  MMSD4148T1G  [SOD-123]
D3  PDS3100Q-13  [PowerDI5]
D5  MMSD4148T1G  [SOD-123]
H16  ICK S 10 X 10 X 6,5  [FE_ICK_S10X10X6_5]
J1  PPPC061LFBN-RC  [Sullins_PPPC061LFBN-RC]  (value not drawn)
J2  61300411121  [WURTH_61300411121]  (value not drawn)
J3  61300311121  [WURTH_61300311121]  (value not drawn)
L1  ValueDisplayed: 100µH  [WE-LHMI_1365]  (hidden comment: 744373965101)
Q1  CSD15380F3  [YJM0003A]
R1  ValueDisplayed: 100  [0603]  (hidden comment: RC0603FR-07100RL)
R2  ValueDisplayed: 100  [0603]  (hidden comment: RC0603FR-07100RL)
R3  ValueDisplayed: 0.082  Value2: 0.75W  [KRL1632G8m]  (hidden comment: KRL1632E-M-R082-F-T5)
R4  ValueDisplayed: 10.0  [0805_HV]  (hidden comment: ERJ-P06F10R0V)
R5  ValueDisplayed: 10.0  [0805_HV]  (hidden comment: ERJ-P06F10R0V)
R6  ValueDisplayed: 10.0k  [0603]  (hidden comment: RC0603FR-0710KL)
R7  ValueDisplayed: 4.87k  [0603]  (hidden comment: RC0603FR-074K87L)
R8  ValueDisplayed: 4.87k  [0603]  (hidden comment: RC0603FR-074K87L)
R9  ValueDisplayed: 21.5k  [0603]  (hidden comment: CRCW060321K5FKEA)
R10  ValueDisplayed: 4.87k  [0603]  (hidden comment: RC0603FR-074K87L)
R11  ValueDisplayed: 21.5k  [0603]  (hidden comment: CRCW060321K5FKEA)
R12  ValueDisplayed: 10.0k  [0603]  (hidden comment: RC0603FR-0710KL)
R13  ValueDisplayed: 34.8k  [0603]  (hidden comment: CRCW060334K8FKEA)
R14  ValueDisplayed: 51.1  [0603]  (hidden comment: RC0603FR-0751R1L)
R15  ValueDisplayed: 51.1  [0603]  (hidden comment: RC0603FR-0751R1L)
R16  ValueDisplayed: 3.74k  [0603]  (hidden comment: CRCW06033K74FKEA)
R17  ValueDisplayed: 51.1  [0603]  (hidden comment: RC0603FR-0751R1L)
R18  ValueDisplayed: 51.1  [0603]  (hidden comment: RC0603FR-0751R1L)
R19  ValueDisplayed: 0  [0603]  (hidden comment: RC0603JR-070RL)
R60  ValueDisplayed: 0  [0603]  (hidden comment: RC0603JR-070RL)
R125  ValueDisplayed: 10.0  [0603]  (hidden comment: RC0603FR-0710RL)
R126  ValueDisplayed: 10.0k  [0603]  (hidden comment: RC0603FR-0710KL)
SH-J3  969102-0000-DA  [SNT-100-BK-G]  (value not drawn)
TP1  TESTPOINT_PIGTAIL  [TESTPOINT_PIGTAIL]  (value not drawn)  (no BOM)
TP2  TESTPOINT_PIGTAIL  [TESTPOINT_PIGTAIL]  (value not drawn)  (no BOM)
TP3  TESTPOINT_PIGTAIL  [TESTPOINT_PIGTAIL]  (value not drawn)  (no BOM)
TP4  TESTPOINT_PIGTAIL  [TESTPOINT_PIGTAIL]  (value not drawn)  (no BOM)
U1  TMP116AIDRVR  [DRV0006A]
U2  TMP116AIDRVR  [DRV0006A]
U3  TPS92515HVDGQR  [DGQ0010E_N]
U4  DAC7311IDCKR  [DCK0006A_N]
U6  SN74LVC1G02DRLR  [DRL0005A]  (parts A,B of 2)
U7  SN74LVC1G175DRYR  [DRY0006A]
U33  TLV3201AIDCKR  [DCK0005A_N]

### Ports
ALERT, BOOST_VOUT/BUCK_VIN, BUCK_DISCHG_COFF, BUCK_OFF, BUCK_VOUT, BUCK_VOUT_OV, DIN_BUCK, SCL, SCLK_BUCK, SDA, ~{BUCK_&_BOOST_VOUT_OV_RESET}, ~{DISCHG_L}, ~{SYNC_BUCK}

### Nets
+2V5REF: R126.1
+3V3A: C10.1 C11.1 R1.1 R2.1 U4.4(AVDD/VREF)
+5V0: C13.2 C14.2 R19.1 R125.2 U6.5(VCC) U7.5(VCC)
ALERT: U1.3(ALERT) U2.3(ALERT) ; port ALERT
BUCK_DISCHG_COFF: R60.2 ; port BUCK_DISCHG_COFF
BUCK_VOUT: D1.2(A) D5.2(A) J1.4 J1.5 J1.6 L1.2 R9.2 R13.2 TP2.1 ; port BUCK_VOUT
GND: C1.2 C2.2 C3.2 C5.2 C6.2 C7.2 C8.2 C9.2 C10.2 C11.2 C12.1 C13.1 C14.1 C91.2 C92.1 C93.2 C94.1 D3.1(A) D3.2(A) J1.1 J1.2 J1.3 J2.1 J2.2 Q1.2(S) R6.1 R12.1 R16.1 TP1.2 TP2.2 TP3.2 TP4.2 U1.2(GND) U1.4(ADD0) U1.7(PAD) U2.2(GND) U2.7(PAD) U3.3(GND) U3.11(DAP) U4.5(GND) U6.3(GND) U7.2(GND) U33.2(V-)
SCL: U1.1(SCL) U2.1(SCL) ; port SCL
SDA: U1.6(SDA) U2.6(SDA) ; port SDA
VCC: C3.1 D2.2(A) R10.2 U3.2(VCC)
~{BUCK_&_BOOST_VOUT_OV_RESET}: U7.6(~{CLR}) ; port ~{BUCK_&_BOOST_VOUT_OV_RESET}
~{DISCHG_L}: R15.2 U6.4(Y) ; port ~{DISCHG_L}
~{SYNC_BUCK}: U4.1(~{SYNC}) ; port ~{SYNC_BUCK}
BOOST_VOUT/BUCK_VIN: C5.1 C6.1 C91.1 D1.1(K) R3.2 U3.8(VIN) ; port BOOST_VOUT/BUCK_VIN
BUCK_OFF: U6.1(A) ; port BUCK_OFF
BUCK_ON: R12.2 R15.1 TP3.1 U3.9(PWM)
BUCK_VOUT_OV: R14.1 ; port BUCK_VOUT_OV
DIN: U4.3(DIN) ; port DIN_BUCK
SCLK: U4.2(SCLK) ; port SCLK_BUCK
NetC1_1: C1.1 R1.2 U1.5(V+)
NetC2_1: C2.1 R2.2 U2.4(ADD0) U2.5(V+)
NetC4_1: C4.1 D3.3(K) L1.1 R4.2 R5.2 TP1.1 U3.5(SW)
NetC4_2: C4.2 D2.1(K) U3.4(BOOT)
NetC7_1: C7.1 R4.1 R5.1
NetC8_1: C8.1 J3.2 U3.10(IADJ)
NetC9_1: C9.1 Q1.3(D) R9.1 R10.1 R11.1 TP4.1 U3.1(COFF)
NetC12_2: C12.2 C92.2 R125.1 U33.5(V+)
NetC93_1: C93.1 R126.2 U33.4(IN-)
NetC94_2: C94.2 R13.1 R16.2 U33.3(IN+)
NetD5_1: D5.1(K) R11.2
NetJ2_3: J2.3 J2.4 R7.1
NetJ3_1: J3.1 R8.2
NetJ3_3: J3.3 R7.2
NetQ1_1: Q1.1(G) R6.2 R60.1
NetR3_1: R3.1 U3.6(DRN) U3.7(CSN)
NetR8_1: R8.1 U4.6(VOUT)
NetR14_2: R14.2 R18.2 U7.4(Q)
NetR17_1: R17.1 U7.1(CLK)
NetR17_2: R17.2 U33.1(OUT)
NetR18_1: R18.1 U6.2(B)
NetR19_2: R19.2 U7.3(D)

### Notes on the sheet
- Temperature Buck Converter
  1001000x
- Temperature
  Buck Inductor
  1001001x
- From MCU
- (near H16) Place on PCB behind U3
- 38 V to 49 V
- To MCU
- From Pre-Boost
- (near TP1) BUCK_SW
- V_IADJ_EXT
- (near J2) 0.246 V  → 0.3 A
- (near J2) +
- (near R7) EXTERNAL
- (near J3) INTERNAL
- (near TP2) BUCK_VOUT
- (near J1) V_LED
- Up to 24 V / 2.4 A
- To LED Board
- (near J2) 2.05 V    → 2.5 A
- V_IADJ_INT
- (near TP3) BUCK_ON
- COFF
- (near R125) BUCK_VOUT OVP
- L to H: VOUT_BOOST_2 rising above 25 V to 26.6 V

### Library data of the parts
C1-C3 C12-C14 = GRM188R71C105KE15D: as C41 on sheet TIDA-01081E2_LED_Board
C4 C92 C93 = GCM188R71C104KA37J: as C63 on sheet TIDA-01081E2_DigitalIO
C5 = GRM32ER71K475KE14L: CAP, CERM, 4.7 µF, 80 V,+/- 10%, X7R, 1210; Manufacturer: MuRata; Polarized: N; CompType: Capacitor; Value: 4.7uF; U/M: EA; Cap_F: 0.0000047; Tolerance_%: 10; Value1: Unknown; VDC_V: 80; Value2: 80V; TaMin_C: -55; TaMax_C: 125; Cap_Case: 1210; AEC Category: Q200; SizeArea_mm2: 8; SizeAreaWB_mm2: 14.7; SizeX_mm: 3.2; SizeY_mm: 2.5; SizeZ_mm: 2.7
C6 = GRM188R72A104KA35D: CAP, CERM, 0.1 µF, 100 V, +/- 10%, X7R, 0603; Manufacturer: MuRata; Polarized: N; CompType: Capacitor; Value: 0.1uF; U/M: EA; Cap_F: 0.0000001; Tolerance_%: 10; Value1: Unknown; VDC_V: 100; Value2: 100V; TaMin_C: -55; TaMax_C: 125; Cap_Case: 0603; AEC Category: Q200
C7 = CGA3E2X7R2A222K080AA: CAP, CERM, 2200 pF, 100 V, +/- 10%, X7R, AEC-Q200 Grade 1, 0603; Manufacturer: TDK; Polarized: N; CompType: Capacitor; Value: 2200pF; U/M: EA; Cap_F: 0.0000000022; Tolerance_%: 10; ESR_ohm: 0.923948; Value1: 0.923948 ohm; VDC_V: 100; Value2: 100V; IRMS_A: 0.295638; TaMin_C: -55; TaMax_C: 125; SizeArea_mm2: 1.28; SizeAreaWB_mm2: 4.68; SizeX_mm: 1.6; SizeY_mm: 0.8; SizeZ_mm: 1; AEC Category: Q200; AEC Qualified: Y
C8 = GCM1885C1H471JA16D: CAP, CERM, 470 pF, 50 V, +/- 5%, C0G/NP0, AEC-Q200 Grade 1, 0603; Manufacturer: MuRata; Polarized: N; CompType: Capacitor; Value: 470pF; U/M: EA; Cap_F: 0.00000000047; Tolerance_%: 5; Value1: Unknown; VDC_V: 50; Value2: 50V; TaMin_C: -55; TaMax_C: 125; SizeArea_mm2: 1.28; SizeAreaWB_mm2: 4.68; SizeX_mm: 1.6; SizeY_mm: 0.8; SizeZ_mm: 1; AEC Category: Q200; AEC Qualified: Y
C9 = GCM1885C1H471JA16D: CAP, CERM, 470 pF, 50 V, +/- 5%, C0G/NP0, 0603_095; Manufacturer: MuRata; Polarized: N; CompType: Capacitor; Value: 470pF; U/M: EA; Cap_F: 0.00000000047; Tolerance_%: 5; Value1: Unknown; VDC_V: 50; Value2: 50V; TaMin_C: -55; TaMax_C: 125; Cap_Case: 0603
C10 = C0603C104K8RACTU: CAP, CERM, 0.1 µF, 10 V, +/- 10%, X7R, 0603; Manufacturer: Kemet; Polarized: N; CompType: Capacitor; Value: 0.1uF; U/M: EA; Cap_F: 0.0000001; Tolerance_%: 10; Value1: Unknown; Value2: 10V; TaMin_C: -55; TaMax_C: 125; SizeArea_mm2: 1.28; SizeAreaWB_mm2: 4.68; SizeX_mm: 1.6; SizeY_mm: 0.8; SizeZ_mm: 1; AEC Category: Q200
C11 = GRM188Z71A106MA73D: CAP, CERM, 10 µF, 10 V, +/- 20%, X7R, 0603; Manufacturer: MuRata; Polarized: N; CompType: Capacitor; Value: 10uF; U/M: EA; Cap_F: 0.00001; Tolerance_%: 20; Value1: Unknown; VDC_V: 10; Value2: 10V; TaMin_C: -55; TaMax_C: 125; SizeArea_mm2: 1.28; SizeAreaWB_mm2: 4.68; SizeX_mm: 1.6; SizeY_mm: 0.8; SizeZ_mm: 1; AEC Category: Q200
C91 = CGA6N3X7R2A225K230AB: CAP, CERM, 2.2 µF, 100 V,+/- 10%, X7R, AEC-Q200 Grade 1, 1210; Manufacturer: TDK; Polarized: N; CompType: Capacitor; Value: 2.2uF; U/M: EA; Cap_F: 0.0000022; Tolerance_%: 10; ESR_ohm: 0.00173; Value1: 0.00173 ohm; VDC_V: 100; Value2: 100V; IRMS_A: 5.59317; TaMin_C: -55; TaMax_C: 125; Cap_Case: 1210; SizeArea_mm2: 8; SizeAreaWB_mm2: 14.7; SizeX_mm: 3.2; SizeY_mm: 2.5; AEC Category: Q200; AEC Qualified: Y; AEC Grade: 1
C94 = 06035A100JAT2A: CAP, CERM, 10 pF, 50 V,+/- 5%, C0G/NP0, 0603; Manufacturer: AVX; Polarized: N; CompType: Capacitor; Value: 10pF; U/M: EA; Cap_F: 0.00000000001; Tolerance_%: 5; ESR_ohm: 0.403; Value1: 0.403 ohm; VDC_V: 50; Value2: 50V; TaMin_C: -55; TaMax_C: 125; SizeArea_mm2: 1.28; SizeAreaWB_mm2: 4.68; SizeX_mm: 1.6; SizeY_mm: 0.8; SizeZ_mm: 1; AEC Category: Q200; Green_Lifecycle: Active; Green_REACh: Passed
D1 = VS-2EFH02HM3/I: Diode, Hyperfast, 200 V, 2 A, AEC-Q101, DO-219AB; Manufacturer: Vishay-Semiconductor; U/M: EA; Vf_V: 0.95; Value: 200V; Value1: 2A; Value2: 0.95V; Io_A: 2; Vr_V: 200; TJmax_C: 175; RJC_CperW: 15; SizeAreaWB_mm2: 13.16; SizeArea_mm2: 6.66; SizeX_mm: 3.7; SizeY_mm: 1.8; SizeZ_mm: 1.08; AEC Category: Q101; AEC Qualified: Y
D2 D5 = MMSD4148T1G: Diode, Switching, 100 V, 0.2 A, SOD-123; Manufacturer: ON Semiconductor; U/M: EA; Vf_V: 1; Value: 100V; Value1: 0.2A; Value2: 1V; Io_A: 0.2; Vr_V: 100; TJmax_C: 150; SizeAreaWB_mm2: 13.095; SizeArea_mm2: 6.545; SizeX_mm: 3.85; SizeY_mm: 1.7; SizeZ_mm: 1.35; AEC Category: Q101
D3 = PDS3100Q-13: Diode, Schottky, 100 V, 3 A, AEC-Q101, PowerDI5; Manufacturer: Diodes Inc.; U/M: EA; Vf_V: 0.76; Value: 100V; Value1: 3A; Value2: 0.76V; Io_A: 3; Vr_V: 100; TJmax_C: 150; SizeAreaWB_mm2: 49.56; SizeArea_mm2: 24.96; SizeX_mm: 6.4; SizeY_mm: 3.9; SizeZ_mm: 1.05; AEC Category: Q101; AEC Qualified: Y
H16 = CMP-0078705-1: Heat Sink, 10x10x6.5mm; Manufacturer: Fischer Elektronik
J1 = PPPC061LFBN-RC: Receptacle, 2.54mm, 6x1, Gold, TH; Manufacturer: Sullins Connector Solutions; SymbolCreator: a0411947; Pitch_mm: 2.54; Gender: Female; Row_Count: 1; Current_A: 3; Voltage_V: 250; Cert_UL: Y
J2 = 61300411121: as J7 on sheet TIDA-01081E2_LED_Board
J3 = 61300311121: as J17 on sheet TIDA-01081E2_DigitalIO
L1 = 744373965101: Inductor, Wirewound, Powdered Iron, 100 µH, 2.6 A, 0.165 ohm, SMD; Manufacturer: Wurth Elektronik; Value: 100uH; Ind_H: 100.0E-6; Imax_A: 2.6; Irms: 2.6A @ 40C rise; Isat: 5.2A @ 20% inductance drop; DCR_ohm: 0.165; Value2: 2.6A; SizeAreaWB_mm2: 210.25; SizeArea_mm2: 156.25; SizeX_mm: 12.5; SizeZ_mm: 6.5; AEC Category: Q200; AEC Qualified: N
Q1 = CSD15380F3: MOSFET, N-CH, 20 V, 0.5 A, YJM0003A (PICOSTAR-3); Manufacturer: Texas Instruments; Alternate Manufacturer: None; SymbolCreator: a0411947; U/M: EA; ChType: N; Value: 20V; VdsMax_V: 20; Value1: 1.46 ohm; Rdson45_ohm: 1.46; Value2: 0.216 nC; QgTyp_nC: 0.216; Vgs_V: 10; IdsMax_A: 0.5; SizeAreaWB_mm2: 2.704; SizeArea_mm2: 0.414; SizeX_mm: 0.69; SizeY_mm: 0.6; SizeZ_mm: 0.35; AEC Category: Q101
R1 R2 = RC0603FR-07100RL: as R55 on sheet TIDA-01081E2_LED_Board
R3 = KRL1632E-M-R082-F-T5: RES, 0.082, 1%, 0.75 W, AEC-Q200 Grade 0, 1206; Manufacturer: Susumu Co Ltd; CompType: Resistor; Value: 0.082; Value_Code: R082; Tolerance_%: 1; Power_W: 0.75; TempCo: 50 ppm/C; SizeArea_mm2: 1.28; SizeX_mm: 0.8; SizeY_mm: 1.6; SizeZ_mm: 0.7; U/M: EA; AEC Category: Q200; AEC Qualified: Y; AEC Grade: 0
R4 R5 = ERJ-P06F10R0V: RES, 10.0, 1%, 0.5 W, AEC-Q200 Grade 0, 0805; Manufacturer: Panasonic; CompType: Resistor; Value: 10.0; Res_ohm: 10; Value_Code: 10R0; Tolerance_%: 1; Power_W: 0.5; Value2: 0.5W; TempCo: 300 ppm/C; SizeArea_mm2: 2.5; SizeX_mm: 2; SizeY_mm: 1.25; SizeZ_mm: 1.45; EIA_Code: E96; U/M: EA; AEC Category: Q200; AEC Qualified: Y; AEC Grade: 0
R6 R12 = RC0603FR-0710KL: as R59 on sheet TIDA-01081E2_LED_Board
R7 R8 R10 = RC0603FR-074K87L: RES, 4.87 k, 1%, 0.1 W, 0603; Manufacturer: Yageo America; CompType: Resistor; Value: 4.87k; Res_ohm: 4870; Value_Code: 4k87; Tolerance_%: 1; Power_W: 0.1; Value2: 0.1W; VDC_V: 150; TempCo: 200 ppm/C; SizeArea_mm2: 1.28; SizeX_mm: 1.6; SizeY_mm: 0.8; EIA_Code: E96; U/M: EA; AEC Category: Q200
R9 R11 = CRCW060321K5FKEA: RES, 21.5 k, 1%, 0.1 W, 0603; Manufacturer: Vishay-Dale; CompType: Resistor; Value: 21.5k; Res_ohm: 21500; Value_Code: 21k5; Tolerance_%: 1; Power_W: 0.1; Value2: 0.1W; VDC_V: 75; TempCo: 100 ppm/C; SizeArea_mm2: 1.28; SizeX_mm: 1.6; SizeY_mm: 0.8; EIA_Code: E96; U/M: EA; AEC Category: Q200
R13 = CRCW060334K8FKEA: RES, 34.8 k, 1%, 0.1 W, 0603; Manufacturer: Vishay-Dale; CompType: Resistor; Value: 34.8k; Res_ohm: 34800; Value_Code: 34k8; Tolerance_%: 1; Power_W: 0.1; Value2: 0.1W; VDC_V: 75; TempCo: 100 ppm/C; SizeArea_mm2: 1.28; SizeX_mm: 1.6; SizeY_mm: 0.8; EIA_Code: E96; U/M: EA; AEC Category: Q200
R14 R15 R17 R18 = RC0603FR-0751R1L: as R57 on sheet TIDA-01081E2_LED_Board
R16 = CRCW06033K74FKEA: RES, 3.74 k, 1%, 0.1 W, 0603; Manufacturer: Vishay-Dale; CompType: Resistor; Value: 3.74k; Res_ohm: 3740; Value_Code: 3k74; Tolerance_%: 1; Power_W: 0.1; Value2: 0.1W; VDC_V: 75; TempCo: 100 ppm/C; SizeArea_mm2: 1.28; SizeX_mm: 1.6; SizeY_mm: 0.8; EIA_Code: E96; U/M: EA; AEC Category: Q200; Green_Lifecycle: Active; Green_REACh: Passed
R19 R60 = RC0603JR-070RL: as R58 on sheet TIDA-01081E2_LED_Board
R125 = RC0603FR-0710RL: RES, 10.0, 1%, 0.1 W, 0603; Manufacturer: Yageo America; CompType: Resistor; Value: 10.0; Res_ohm: 10; Value_Code: 10R0; Tolerance_%: 1; Power_W: 0.1; Value2: 0.1W; VDC_V: 150; TempCo: 200 ppm/C; SizeArea_mm2: 1.28; SizeX_mm: 1.6; SizeY_mm: 0.8; EIA_Code: E96; U/M: EA; AEC Category: Q200; Green_Lifecycle: Active; Green_REACh: Passed
R126 = RC0603FR-0710KL: RES, 10.0 k, 1%, 0.1 W, 0603; Manufacturer: Yageo America; CompType: Resistor; Value: 10.0k; Res_ohm: 10000; Value_Code: 10k0; Tolerance_%: 1; Power_W: 0.1; Value2: 0.1W; VDC_V: 150; TempCo: 200 ppm/C; SizeArea_mm2: 1.28; SizeX_mm: 1.6; SizeY_mm: 0.8; EIA_Code: E96; U/M: EA; AEC Category: Q200; Green_Lifecycle: Active; Green_REACh: Passed
SH-J3 = 969102-0000-DA: as SH-J5 on sheet TIDA-01081E2_LED_Board
TP1-TP4 = TESTPOINT_PIGTAIL: as TP24 on sheet TIDA-01081E2_DigitalIO
U1 U2 = TMP116AIDRVR: as U15 on sheet TIDA-01081E2_LED_Board
U3 = TPS92515HVDGQR: 2A LED Driver with Integrated NFET, High-Side Current Sense, and Shunt PWM Dimming Capable, DGQ0010E (VSSOP-10); Alternate PartNumber: TPS92515HVDGQT; Manufacturer: Texas Instruments; SymbolCreator: Altium; SizeArea_mm2: 14.64; SizeAreaWB_mm2: 23.52; SizeX_mm: 4.88; SizeY_mm: 3; SizeZ_mm: 1.1; CompType: IC; U/M: EA
U4 = DAC7311IDCKR: 12-bit, single-channel, ultra-low power DAC in 6-pin SC70 package for battery powered applications, DCK0006A (SOT-SC70-6); Alternate PartNumber: DAC7311IDCKT; Manufacturer: Texas Instruments; SymbolCreator: a0411947; SizeArea_mm2: 4.2; SizeAreaWB_mm2: 9.3; SizeX_mm: 2.1; SizeY_mm: 2; SizeZ_mm: 1.1; CompType: IC; U/M: EA
U6 = SN74LVC1G02DRLR: Single 2-Input Positive-NOR Gate, DRL0005A, LARGE T&R; Manufacturer: Texas Instruments; Alternate PartNumber: Equivalent; VCC(Min)(V): 1.65; VCC(Max)(V): 5.5; Output Type: CMOS; ICC @ Nom Voltage(Max)(mA): 0.01; Input Type: CMOS/TTL; Bits(#): 1; F @ Nom Voltage(Max)(Mhz): 150; Rating: Catalog; Technology Family: LVC; Voltage(Nom)(V): 1.8,2.5,3.3,5; Schmitt Trigger: No; Output Drive (IOL/IOH)(Max)(mA): 32/-32; tpd @ Nom Voltage(Max)(ns): 8,5.5,4.5,4; Logic: True; Gate Type: NOR
U7 = SN74LVC1G175DRYR: Single D-Type Flip-Flop with Asynchronous Clear, DRY0006A, LARGE T&R; Manufacturer: Texas Instruments; Alternate PartNumber: Equivalent; VCC(Min)(V): 1.65; VCC(Max)(V): 5.5; Output Type: CMOS; ICC @ Nom Voltage(Max)(mA): 0.01; Input Type: CMOS/TTL; Bits(#): 1; F @ Nom Voltage(Max)(Mhz): 150; Rating: Catalog; Technology Family: LVC; Voltage(Nom)(V): 1.8,2.5,3.3,5; Schmitt Trigger: No; Output Drive (IOL/IOH)(Max)(mA): 32/-32; tpd @ Nom Voltage(Max)(ns): 13.4,7.1,5.7,4; Logic: True
U33 = TLV3201AIDCKR: 40ns, micro-Power, Rail-to-Rail Input, Single-Channel Comparator with Push-Pull Outputs, DCK0005A (SOT-SC70-5); Alternate PartNumber: TLV3201AIDCKT; Manufacturer: Texas Instruments; SizeArea_mm2: 4.2; SizeAreaWB_mm2: 9.3; SizeX_mm: 2.1; SizeY_mm: 2; SizeZ_mm: 1.1; CompType: IC; U/M: EA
